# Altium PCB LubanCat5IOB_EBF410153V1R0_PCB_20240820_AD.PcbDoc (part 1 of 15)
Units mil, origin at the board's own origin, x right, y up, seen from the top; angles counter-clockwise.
Board outline 6811.02 x 4055.12 mil, 6 copper layers (TOP, GND02, ART03, ART04, PWR05, BOTTOM), stack 59.279 mil thick; 981 components, 783 nets, 3627 pads, 2669 vias.
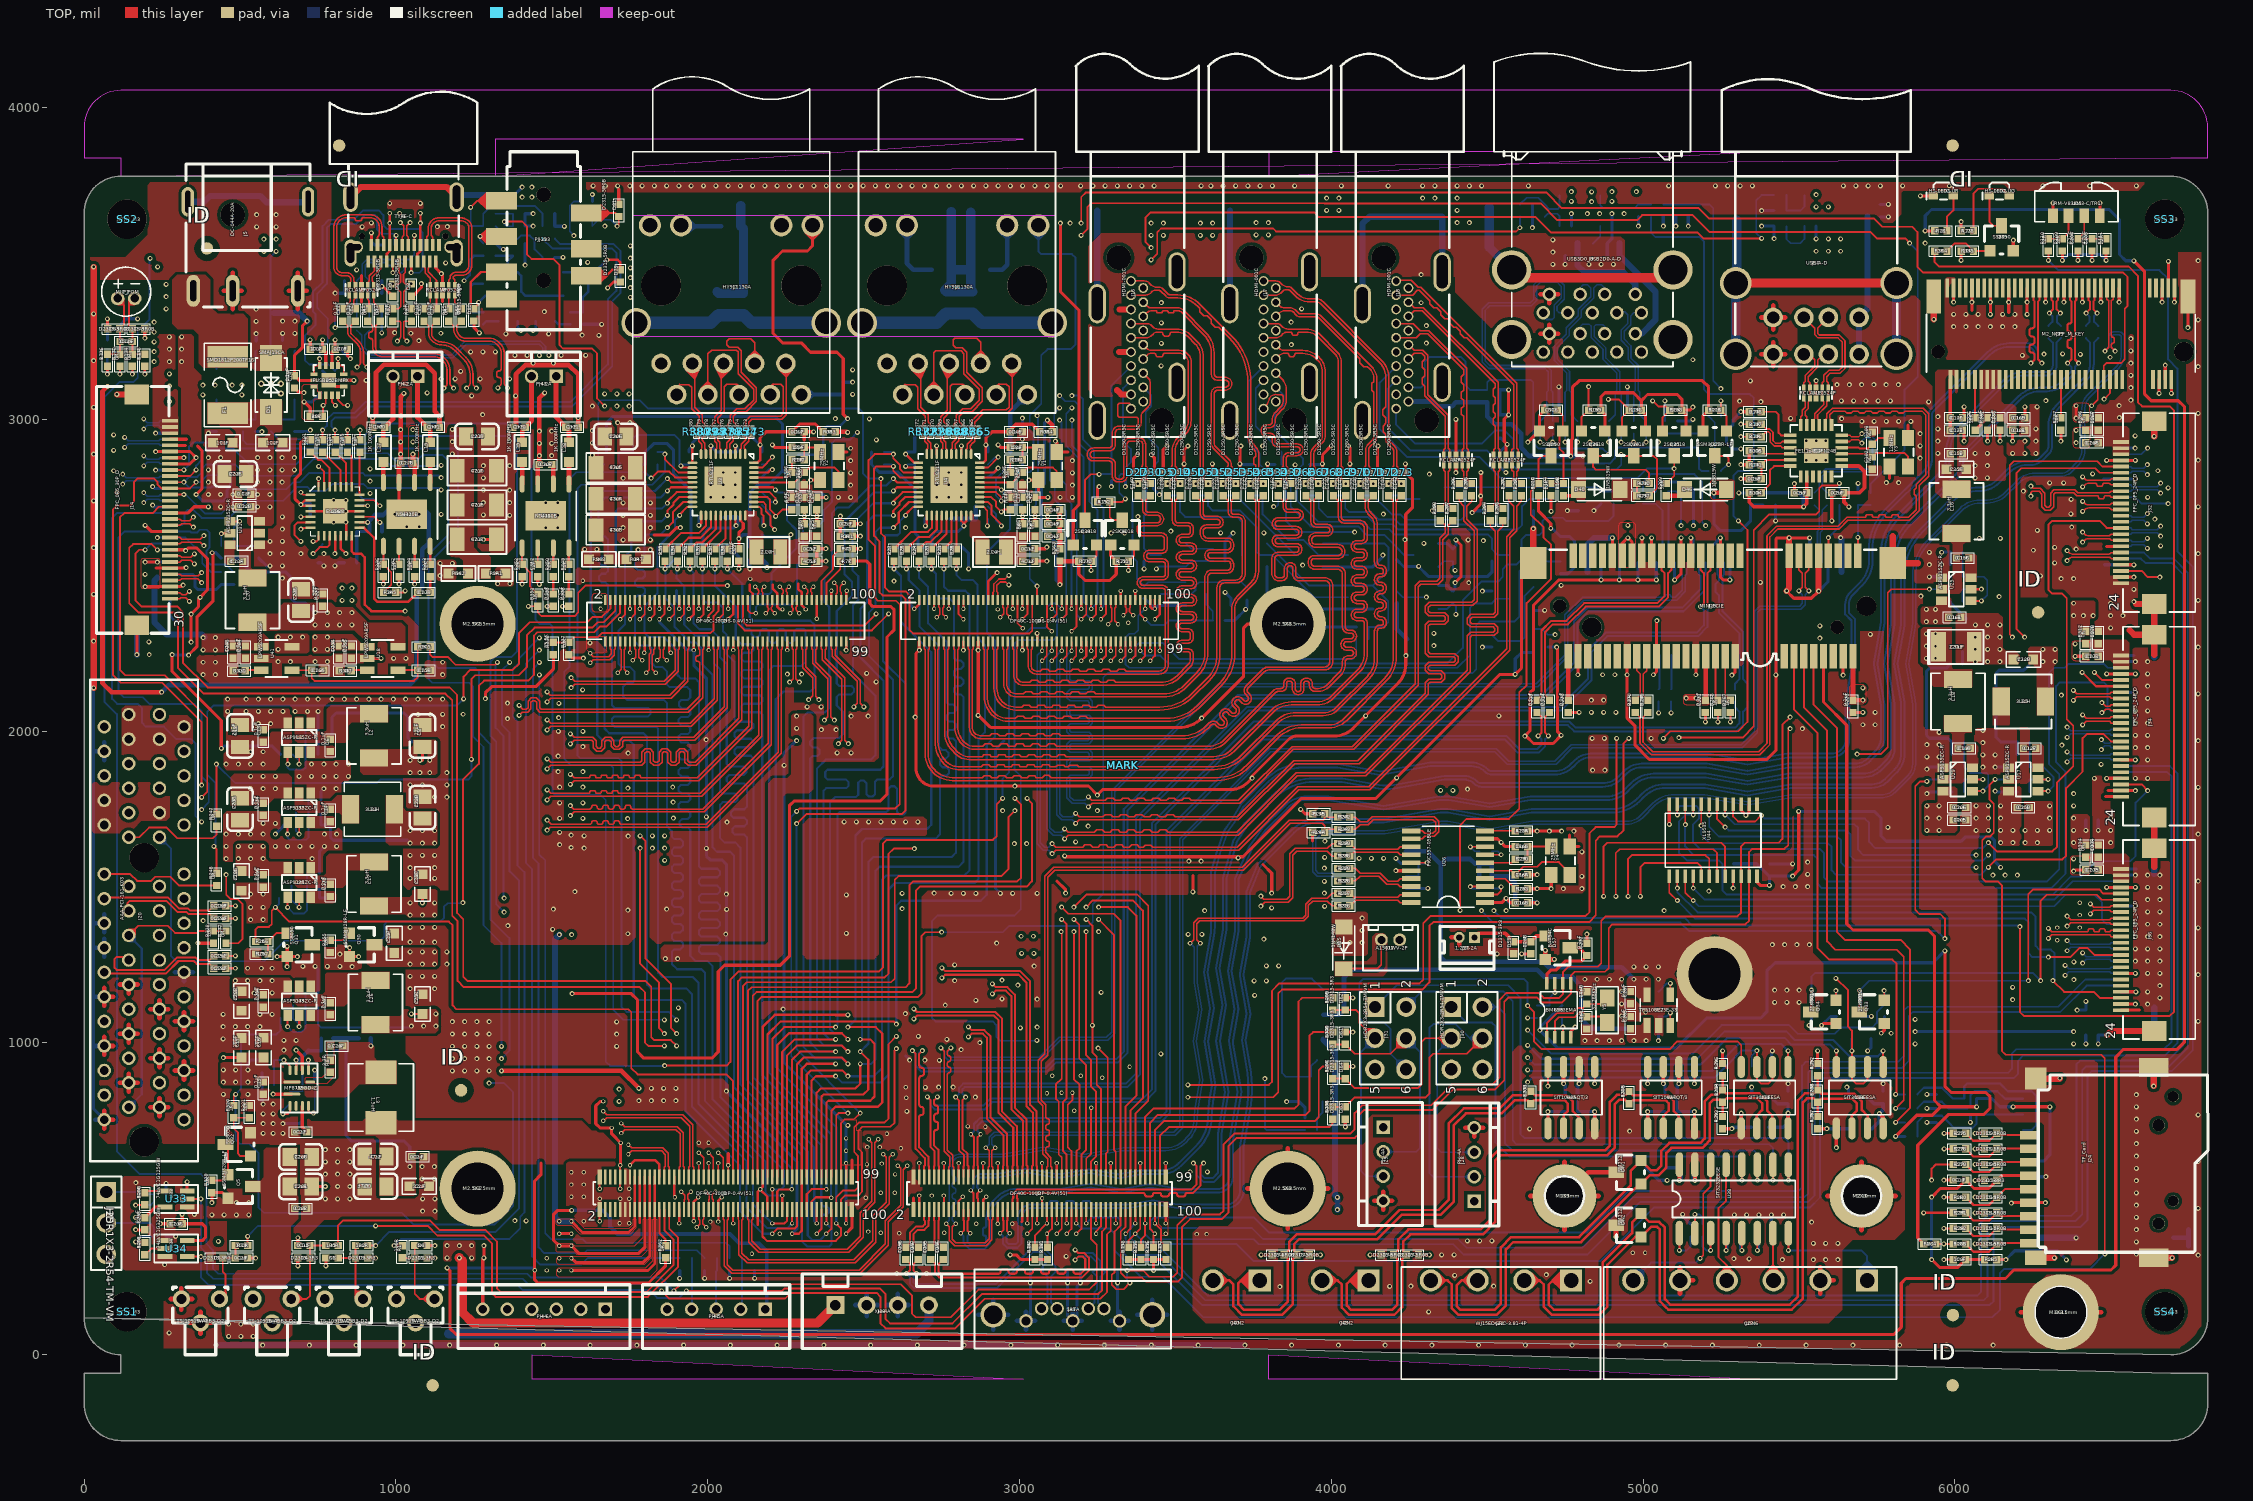
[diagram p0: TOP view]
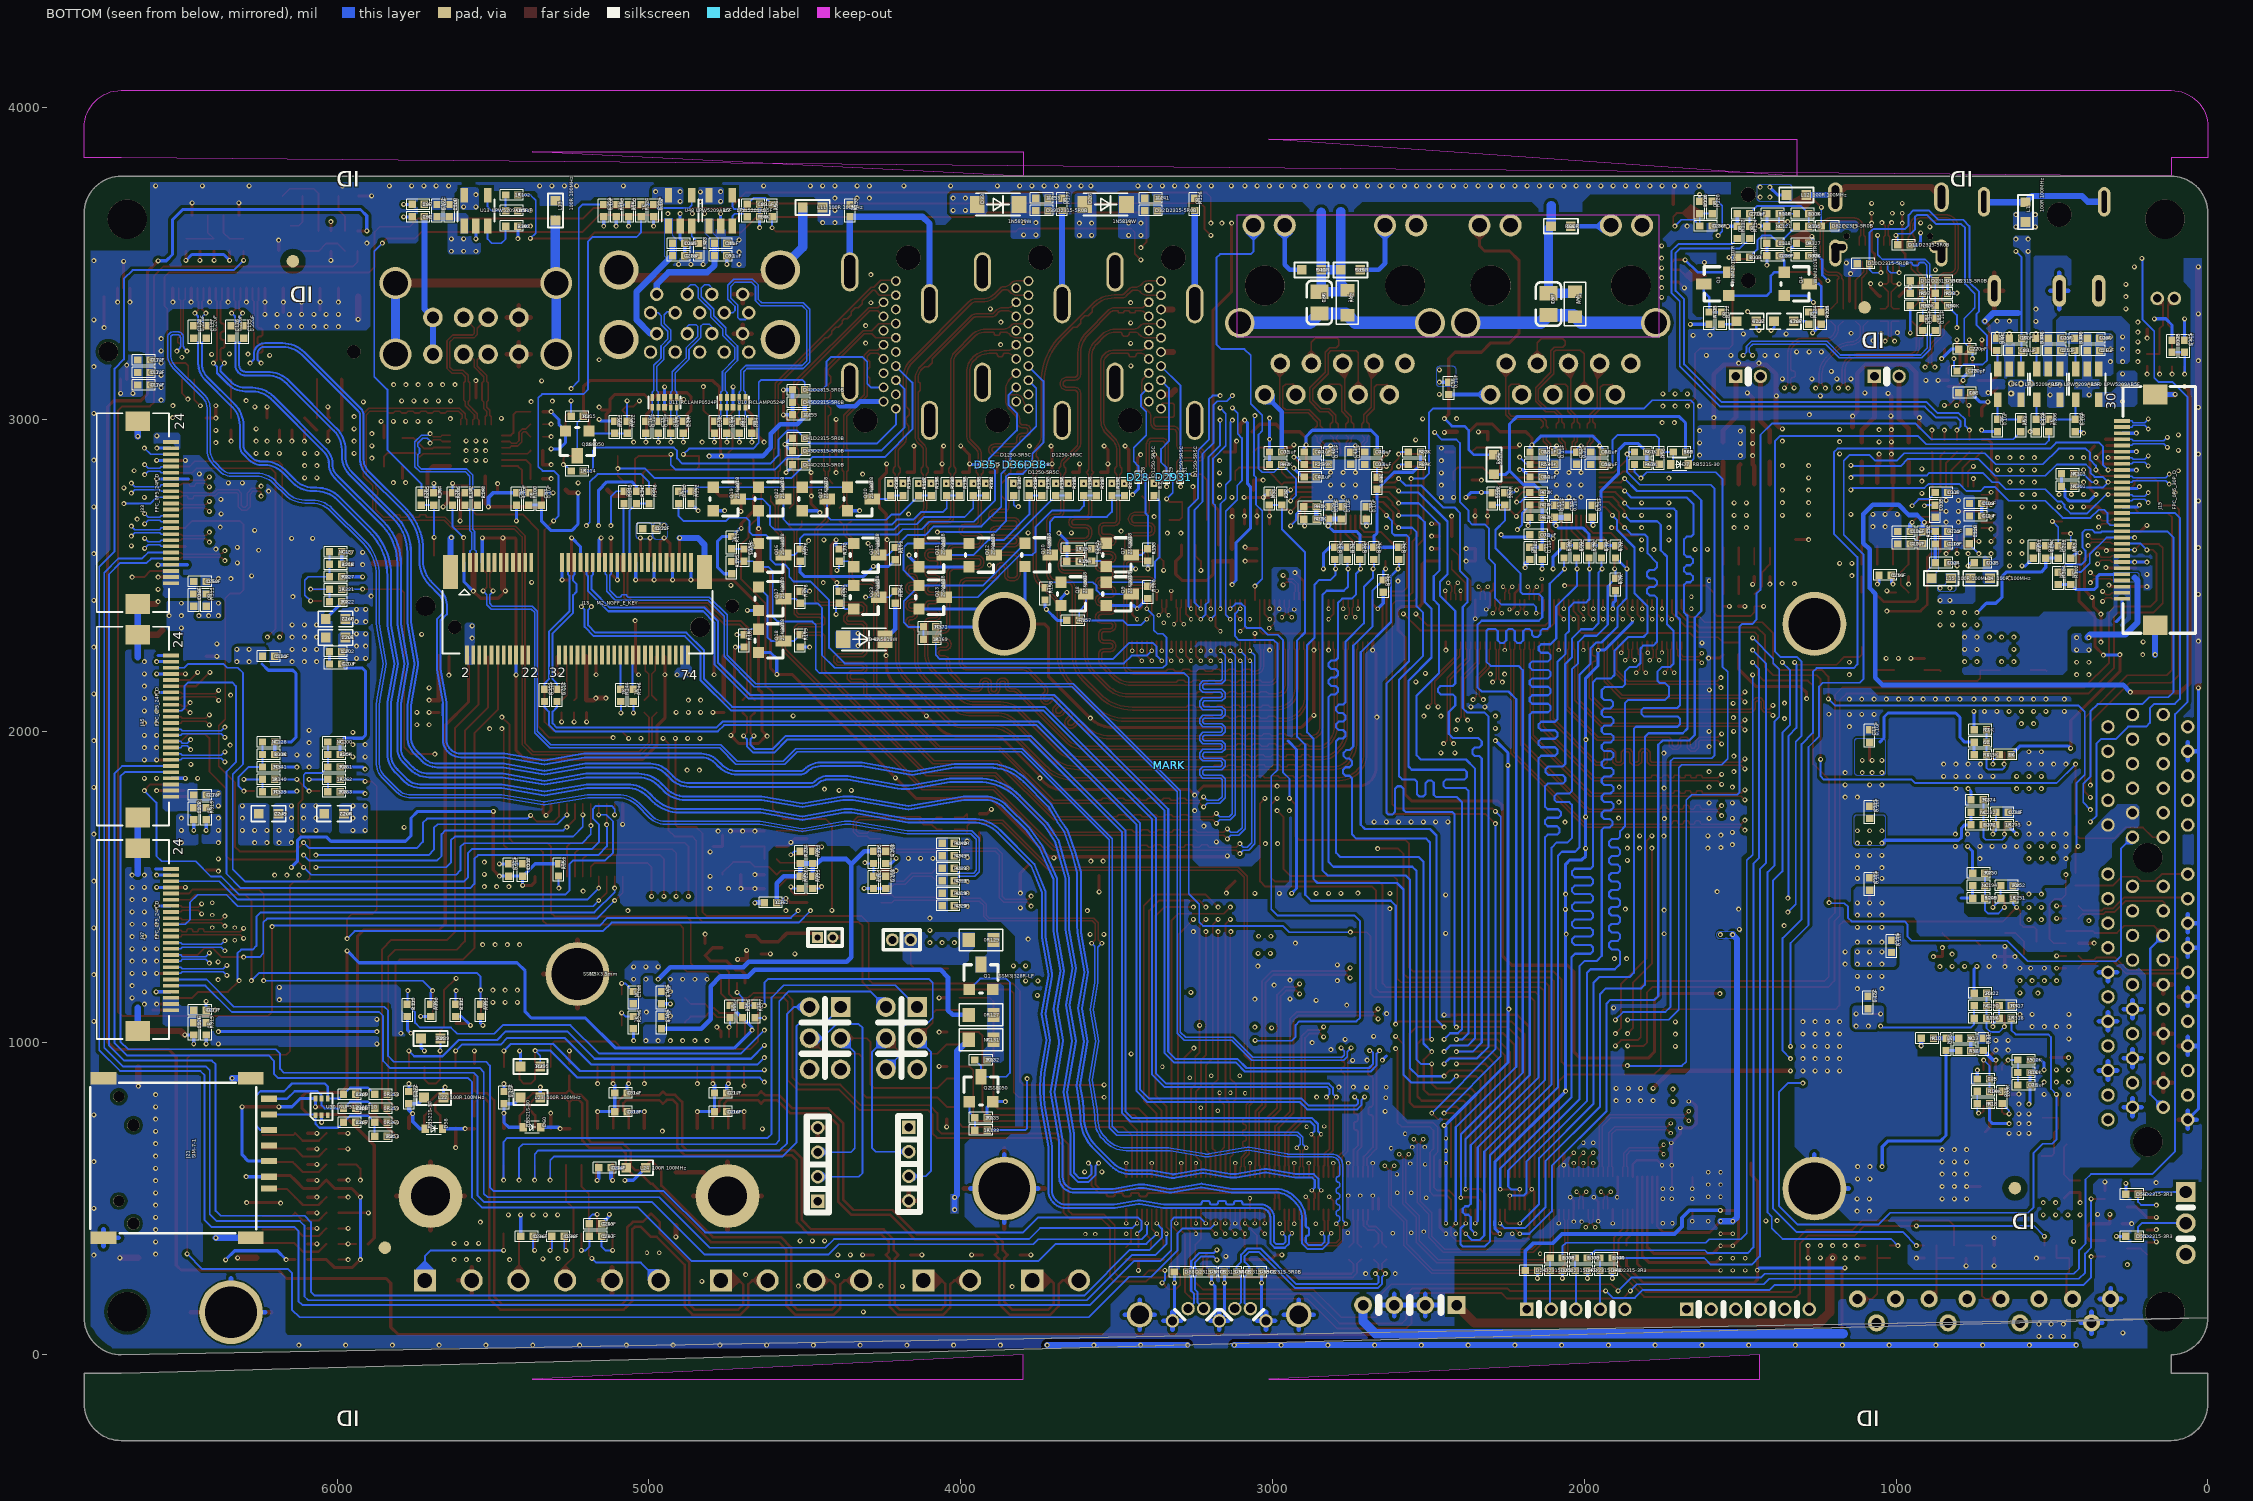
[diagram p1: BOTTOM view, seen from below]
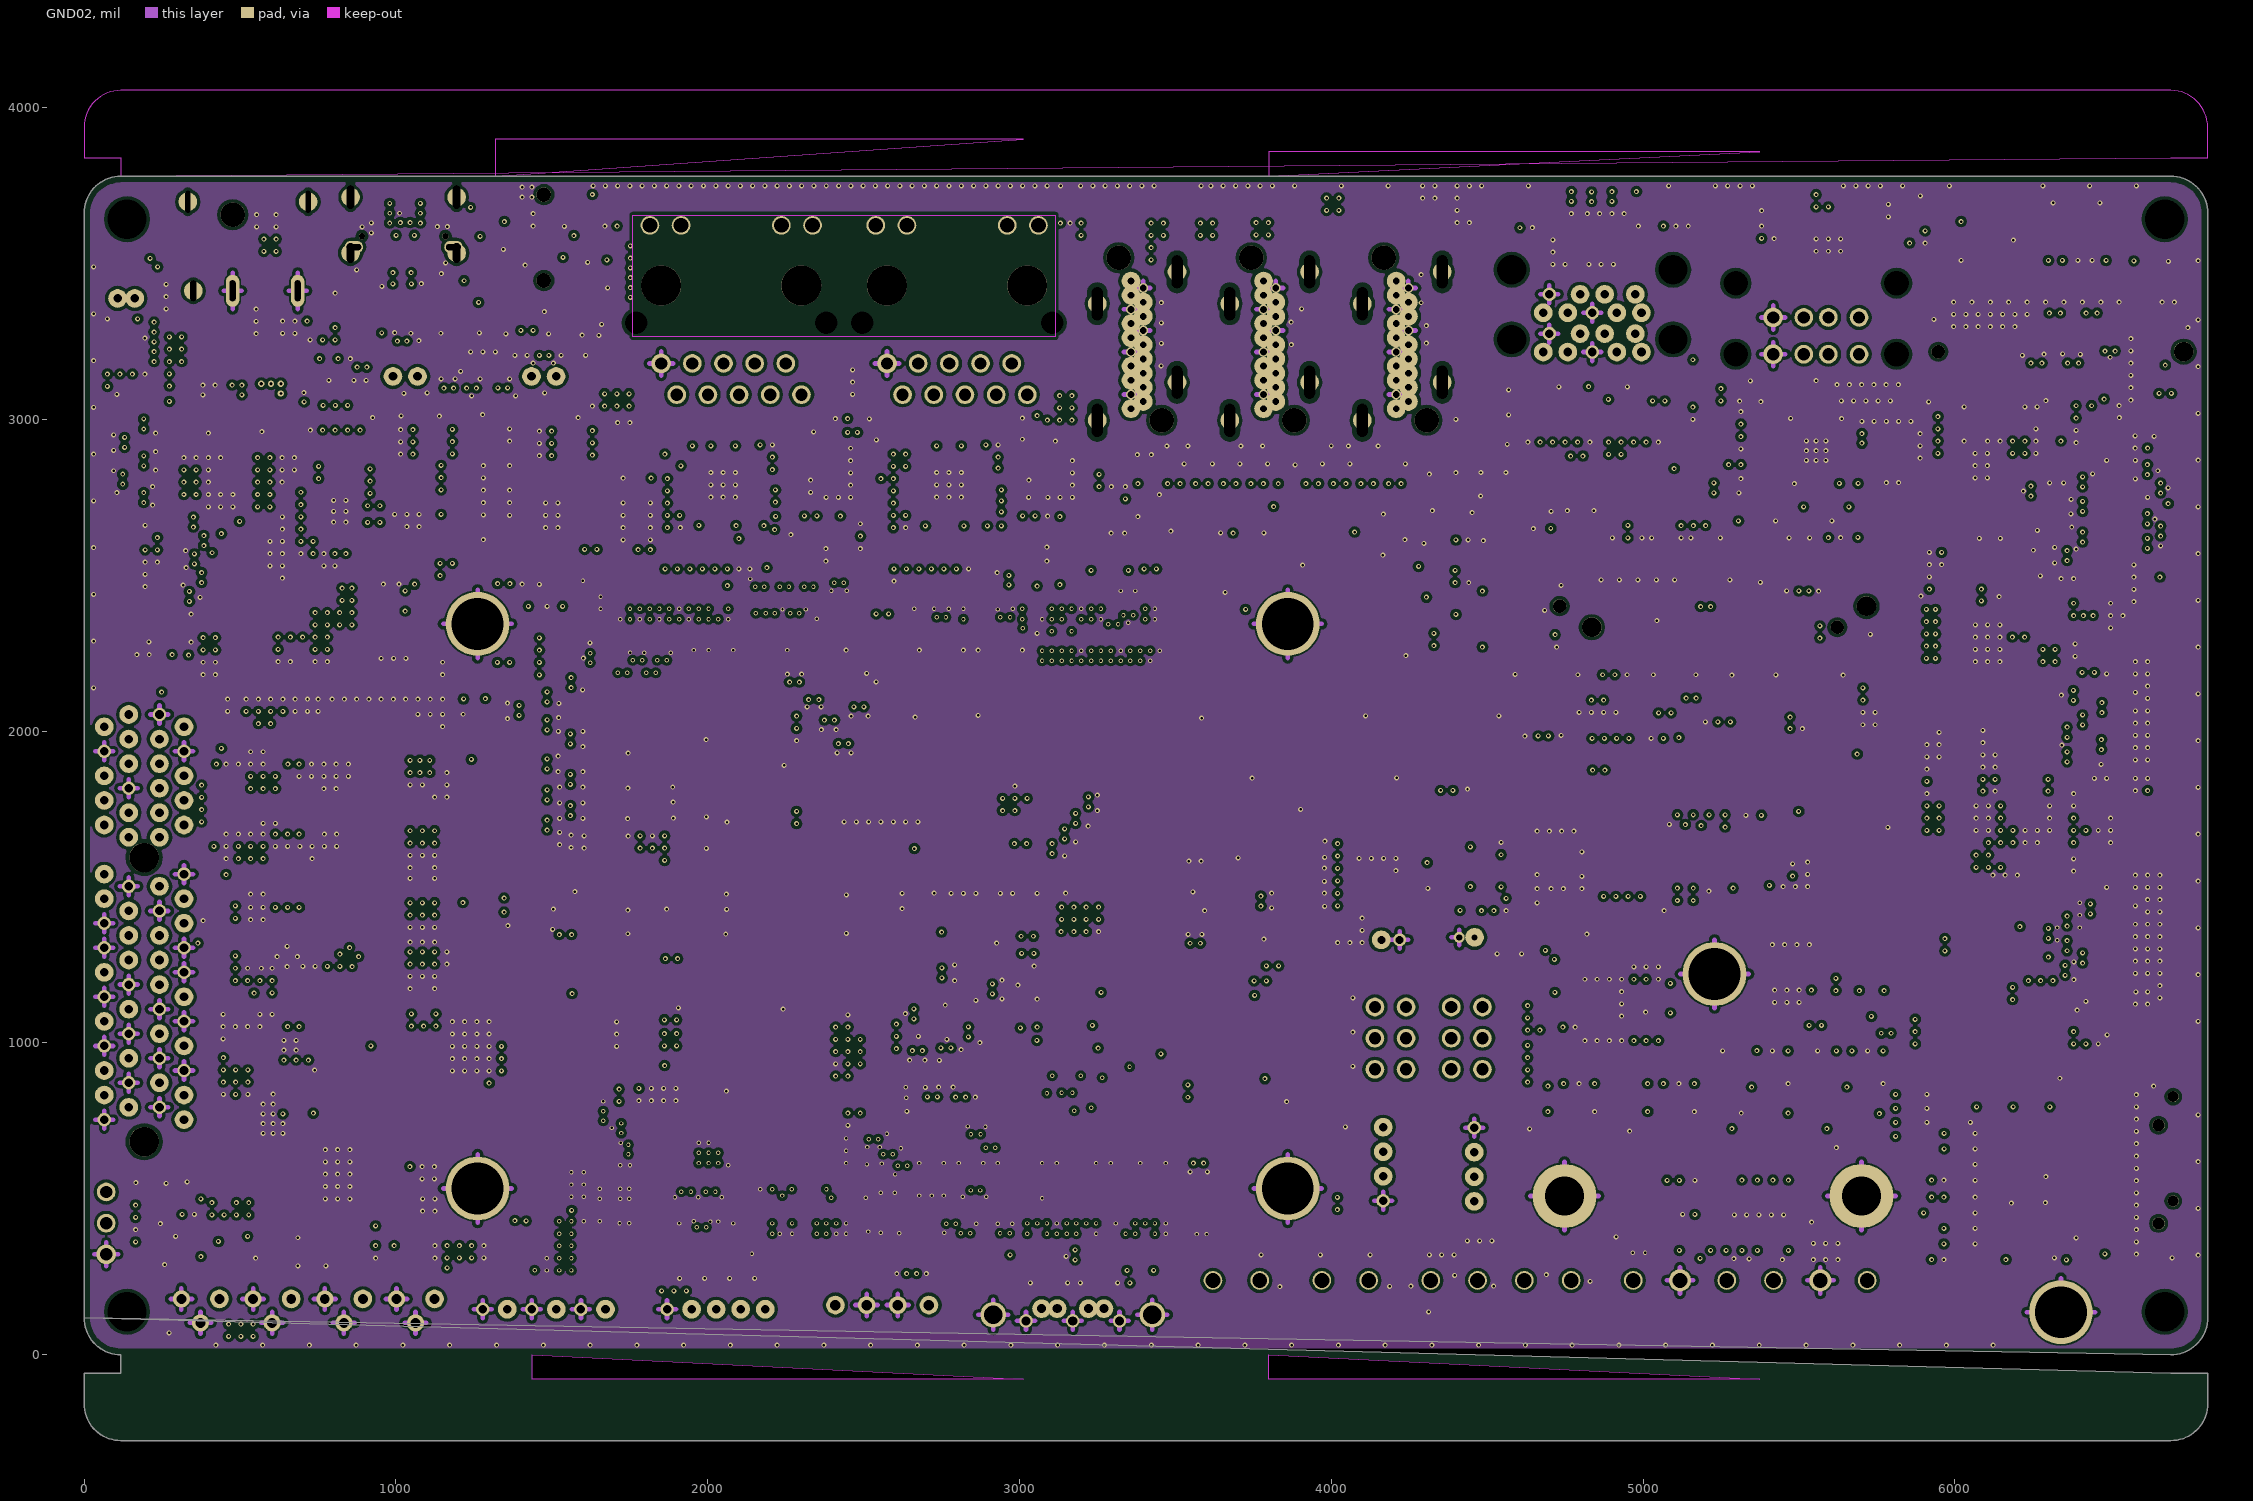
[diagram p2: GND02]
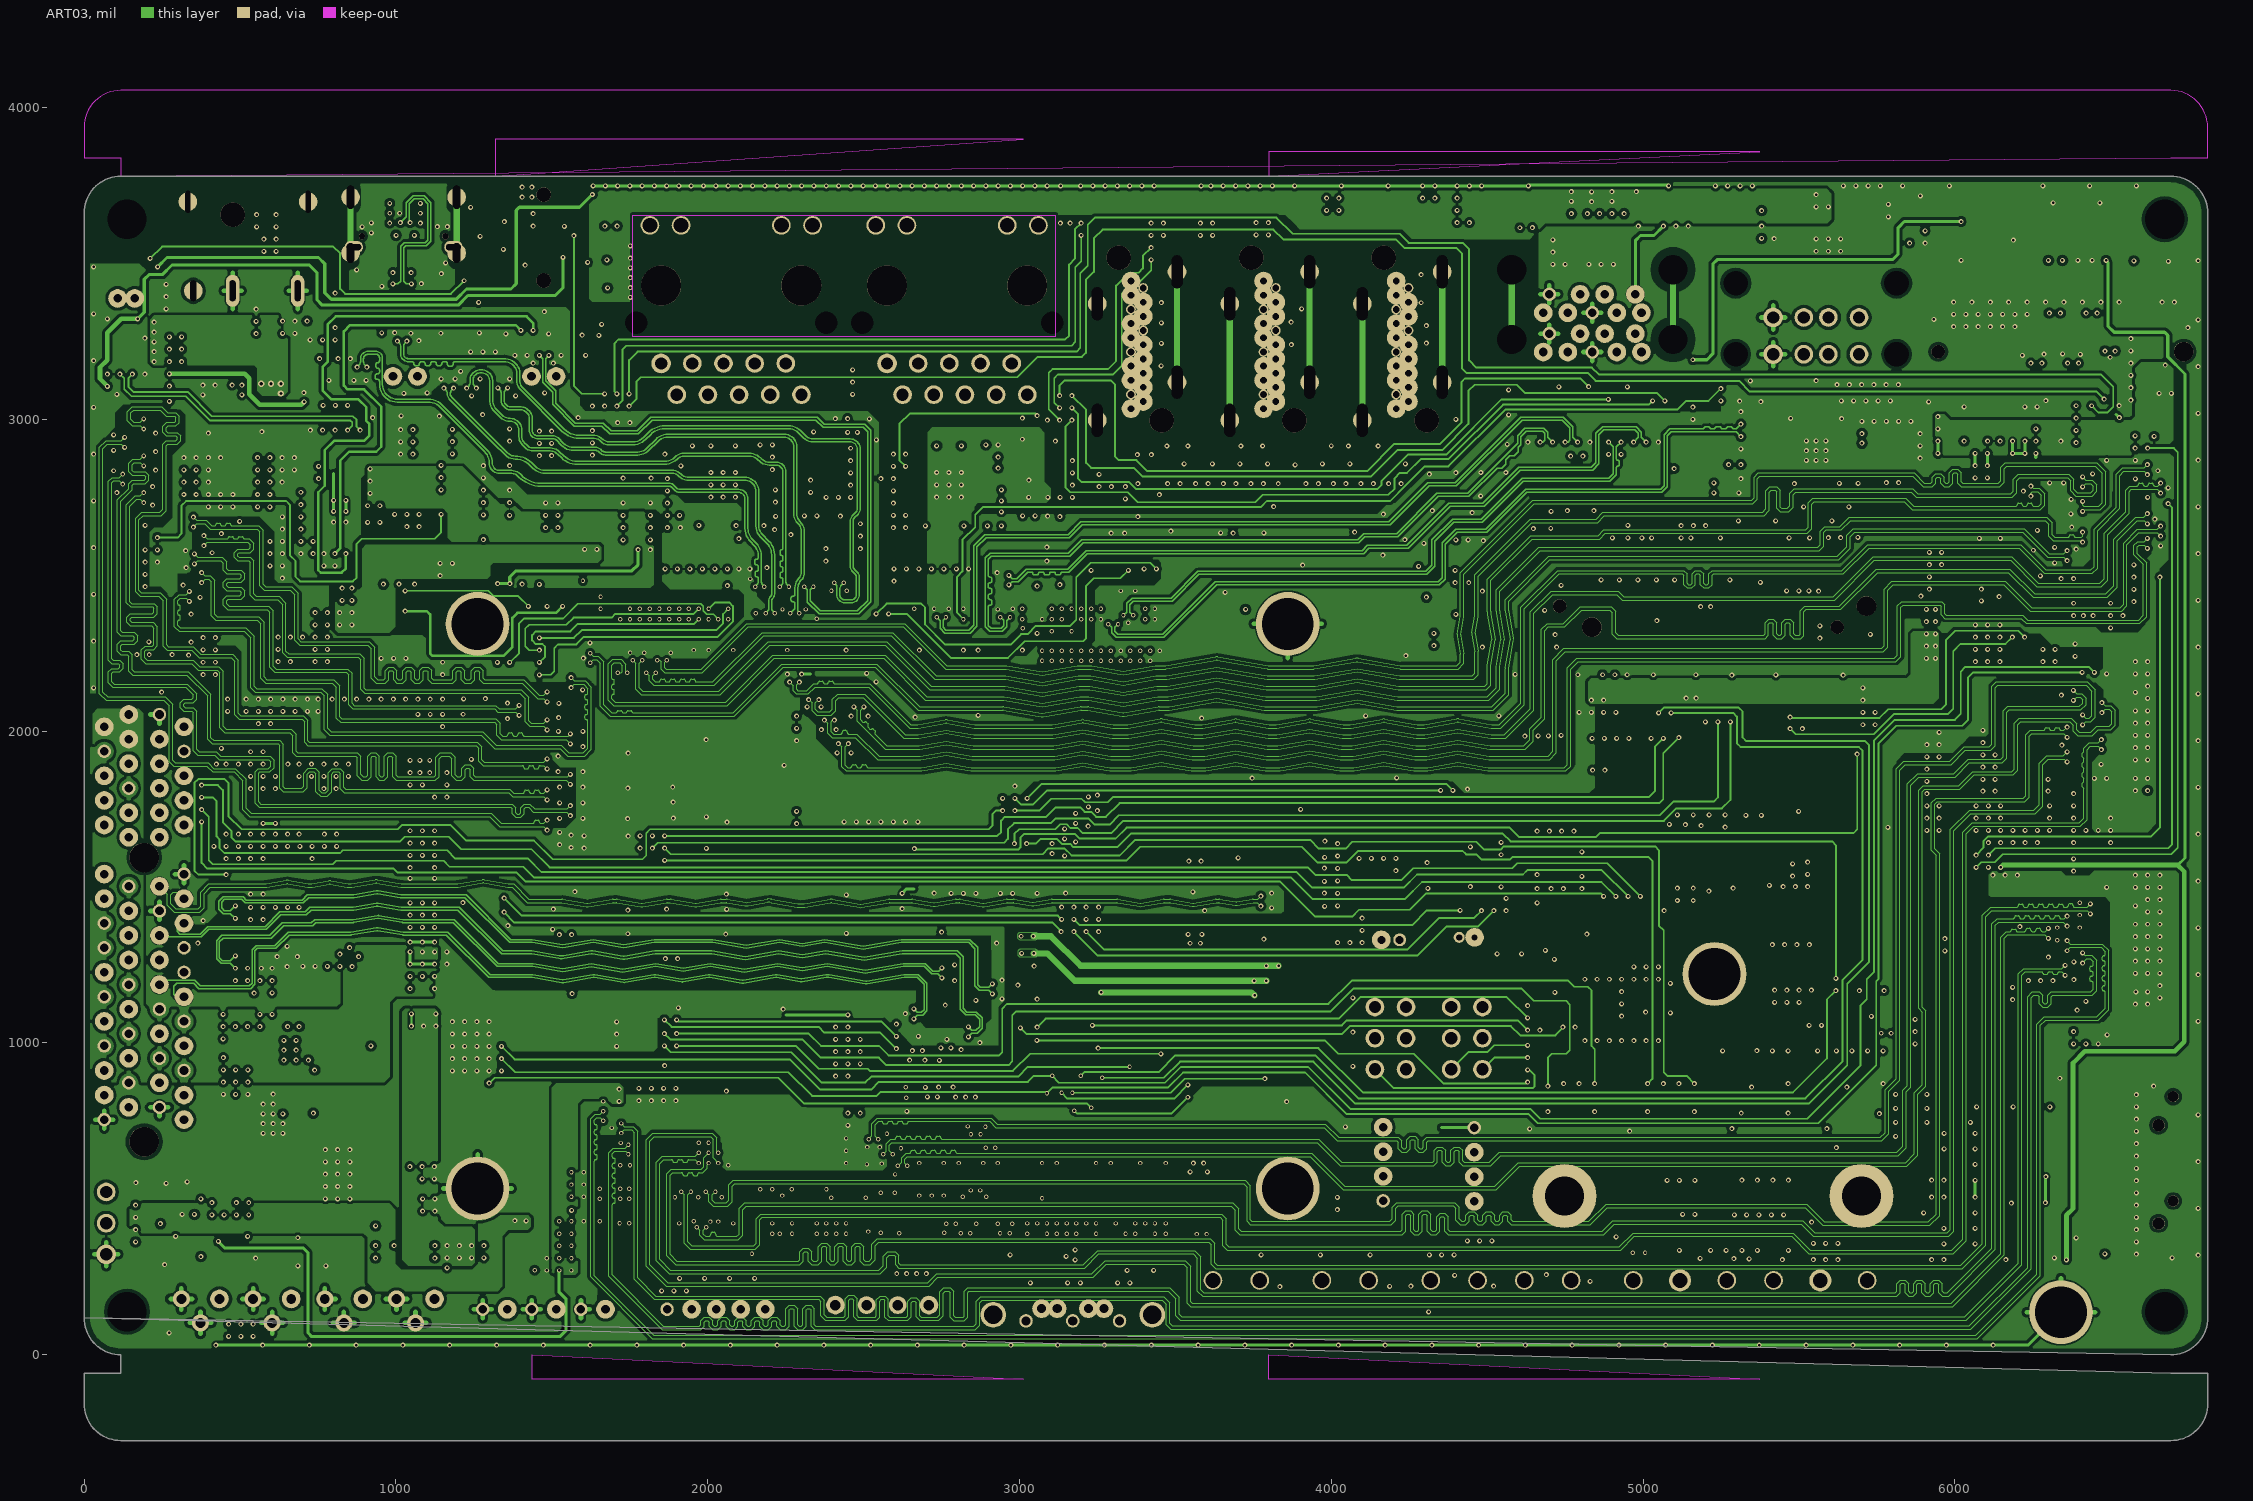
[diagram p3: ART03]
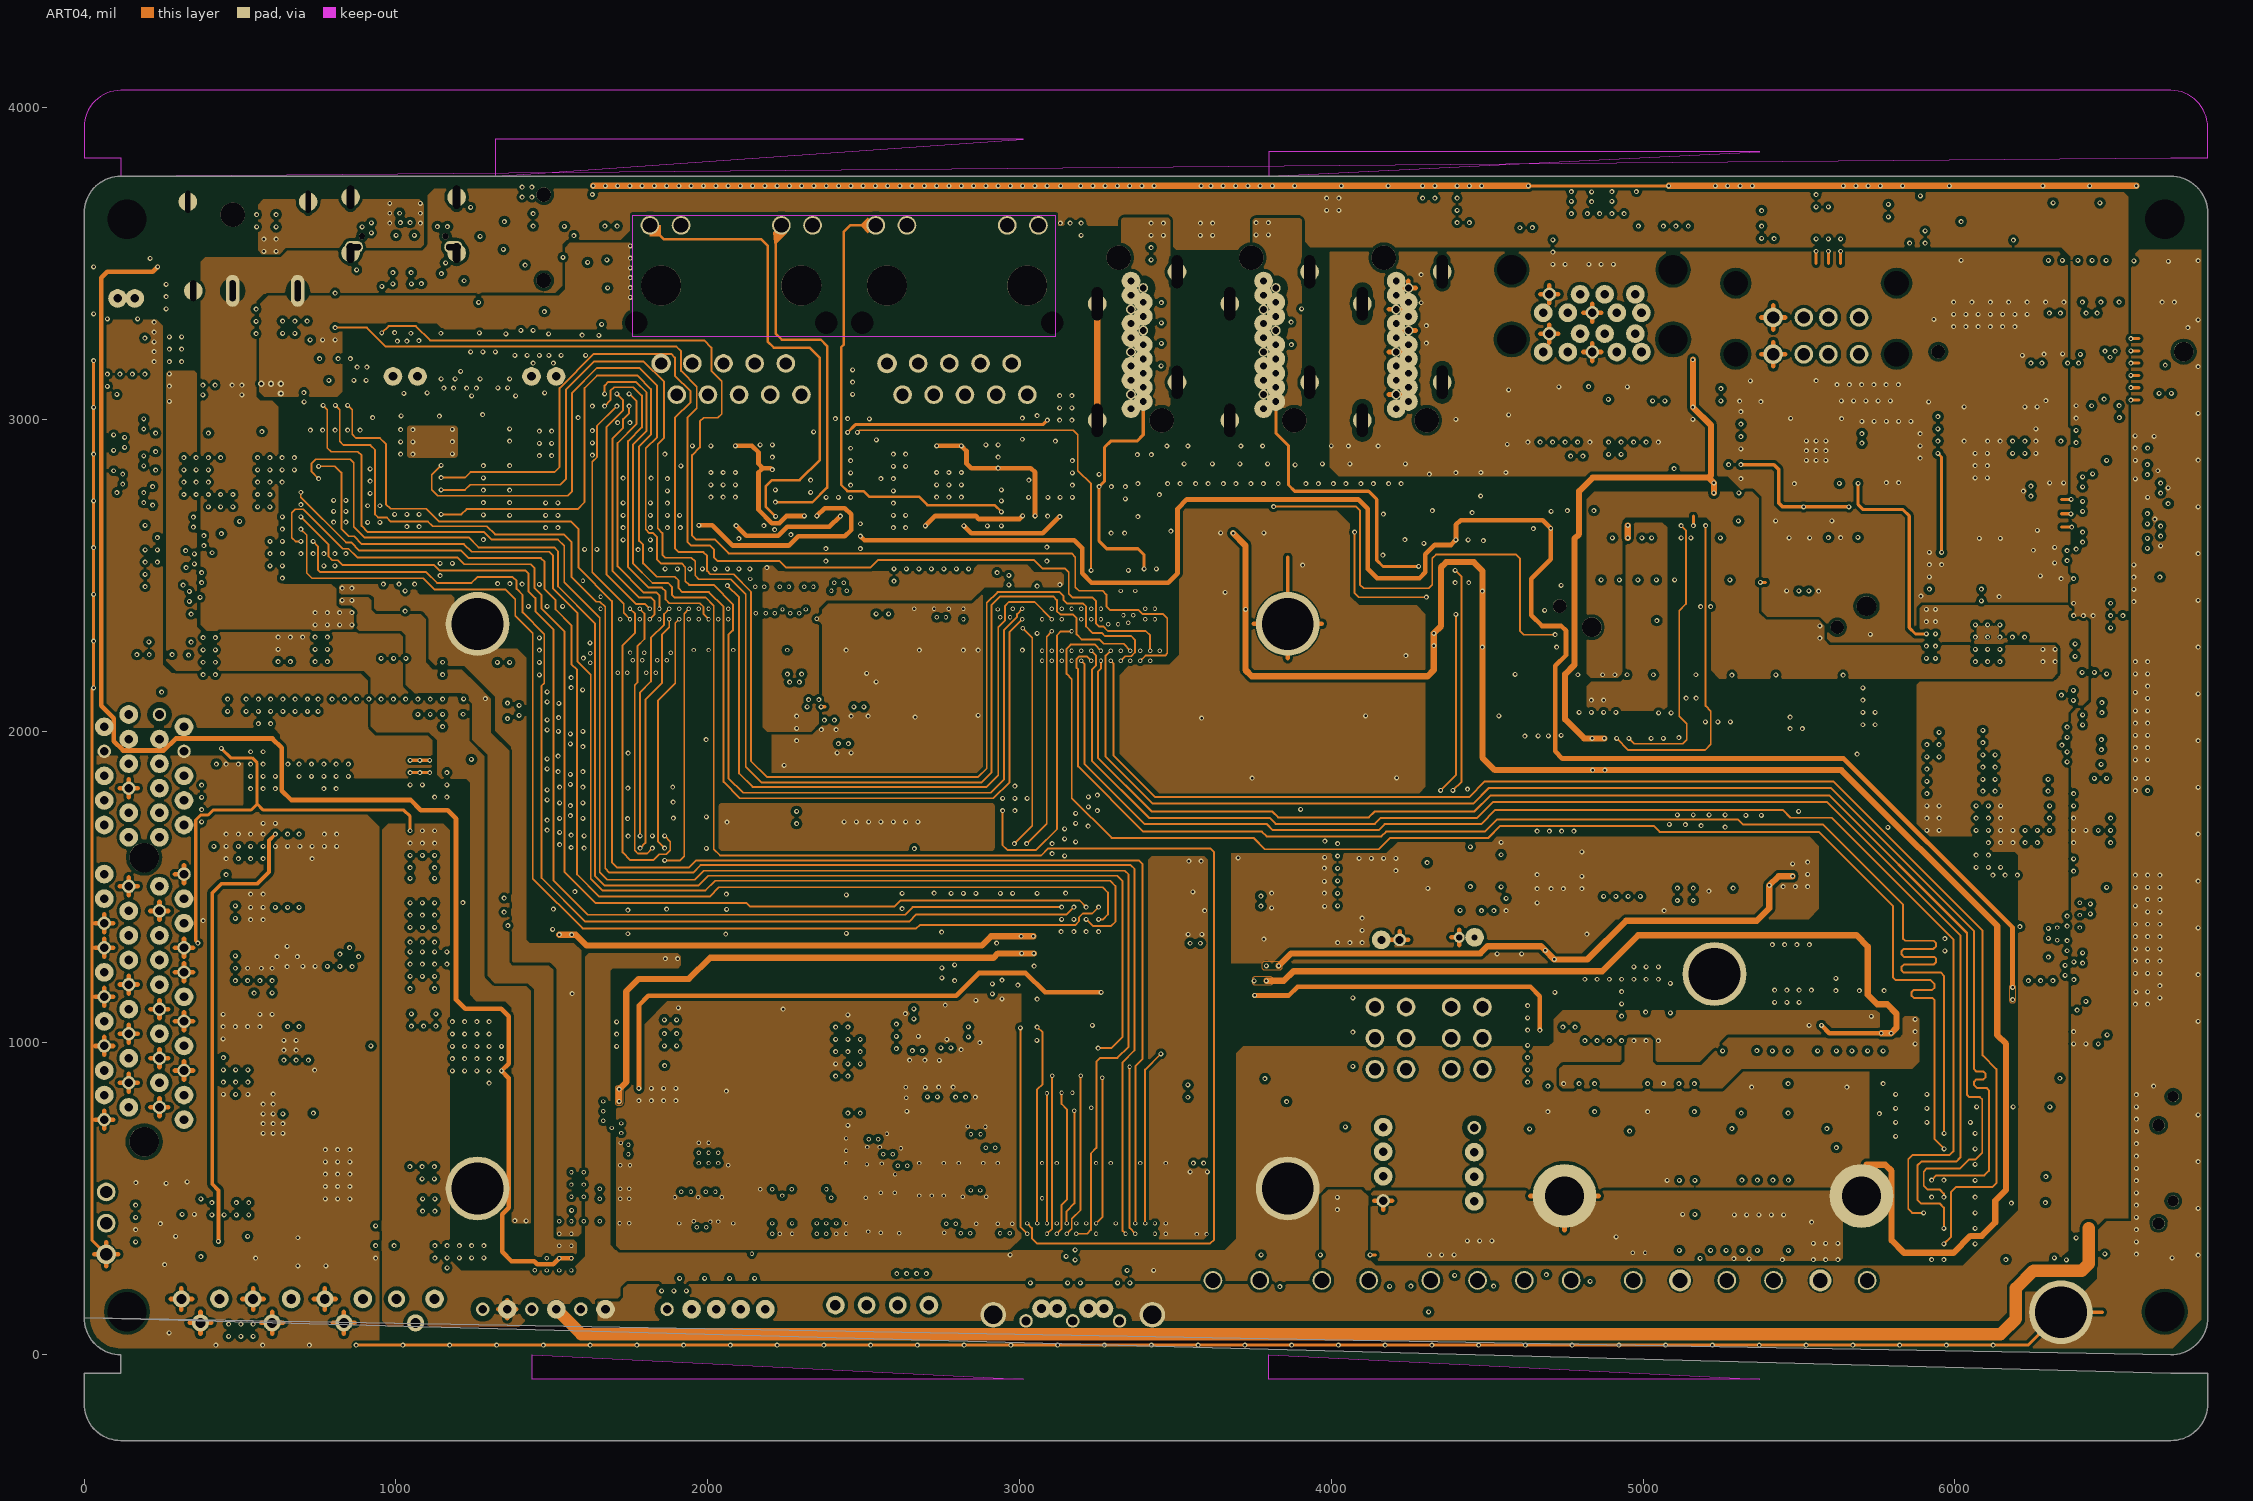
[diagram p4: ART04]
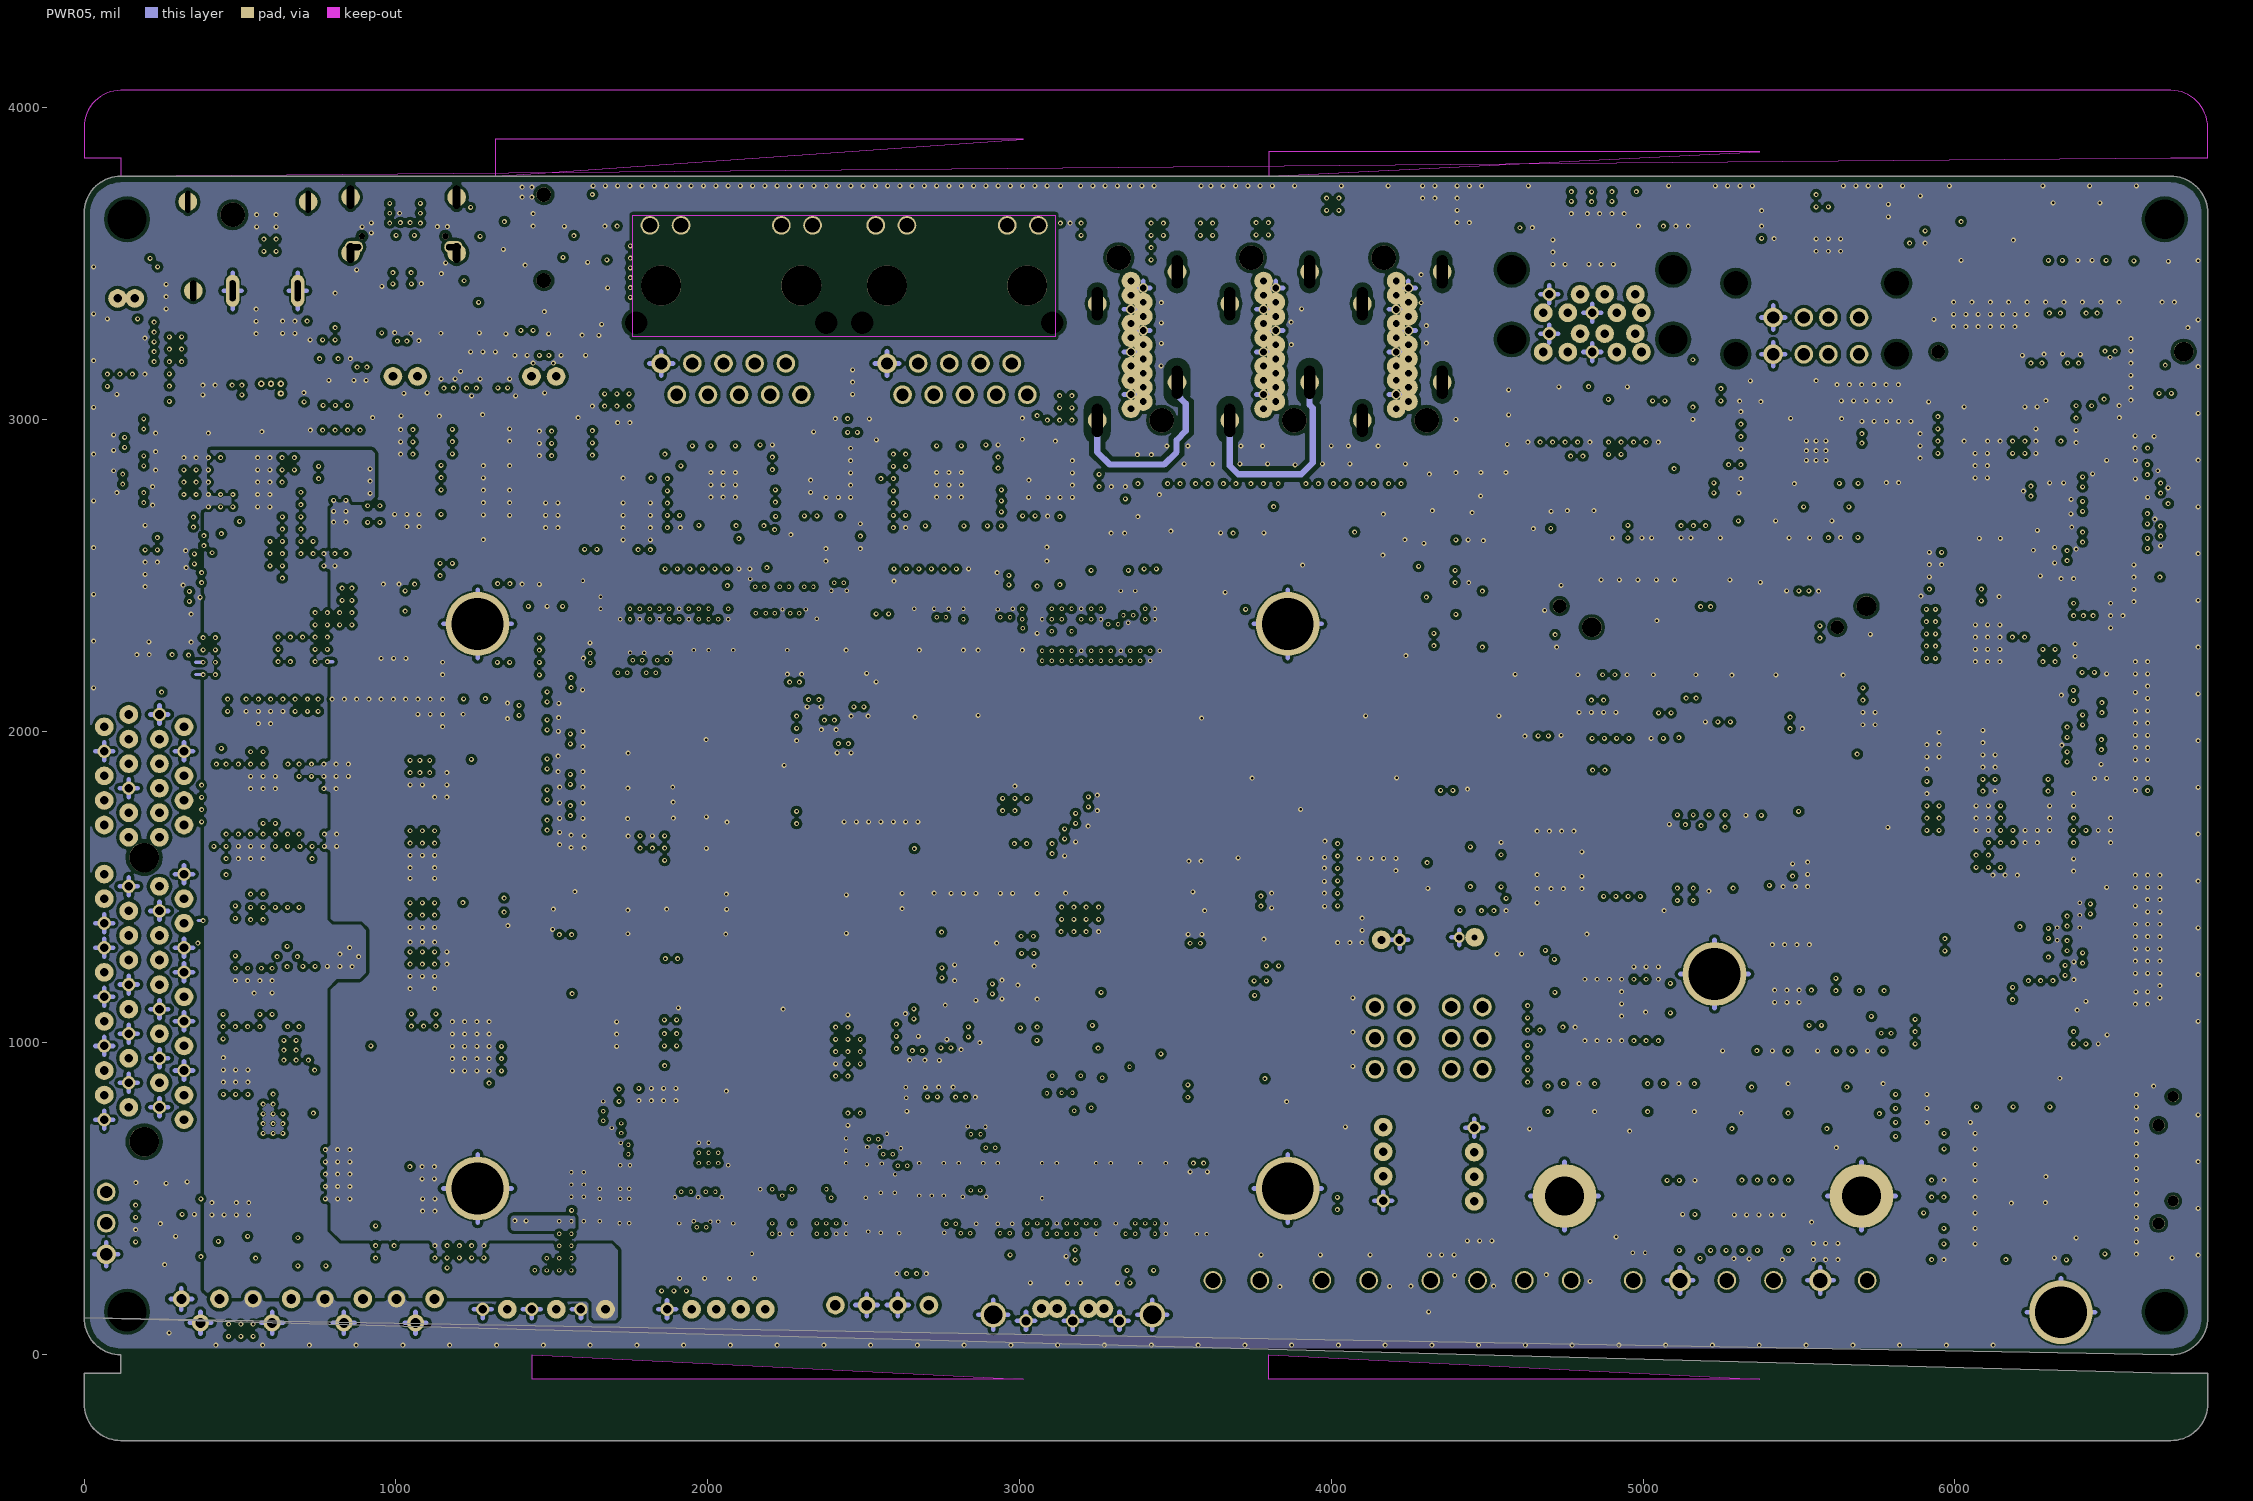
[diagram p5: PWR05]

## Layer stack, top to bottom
Top Solder: solder mask 0.4, Solder Resist, Dk 3.5
TOP: signal copper 0.71
Dielectric 1: core 4.3031, FR-4, Dk 4.5
GND02: signal copper 1.2
Dielectric2: core 5.1, FR-4, Dk 4.5
ART03: signal copper 1.2
Dielectric3: core 34.2529, FR-4, Dk 4.5
ART04: signal copper 1.2
Dielectric4: core 5.1, FR-4, Dk 4.5
PWR05: signal copper 1.2
Dielectric5: core 4.3031, FR-4, Dk 4.5
BOTTOM: signal copper 0.71
Bottom Solder: solder mask 0.4, Solder Resist, Dk 3.5

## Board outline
6692.91,-59.05 6811.02,-59.05 6811.02,-157.48 cw(c6692.91,-157.48) 118.11,-275.59 cw(c118.11,-157.48) 0,-59.05 118.11,-59.05 118.11,0 cw(c118.11,118.11) 6692.91,0 ccw(c6692.91,118.11) 6811.02,3661.42 ccw(c6692.91,3661.42) 118.11,3779.53 ccw(c118.11,3661.42) 0,118.11
cut-out: 6692.91,3838.58 6811.02,3838.58 6811.02,3937.01 ccw(c6692.91,3937.01) 118.11,4055.12 ccw(c118.11,3937.01) 0,3838.58 118.11,3838.58 118.11,3779.53
cut-out: 3011.81,-78.74 1437.01,-78.74 1437.01,0
cut-out: 5374.01,-78.74 3799.21,-78.74 3799.21,0
cut-out: 5374.01,3858.27 3799.21,3858.27 3799.21,3779.53
cut-out: 3011.81,3897.64 1318.9,3897.64 1318.9,3779.53

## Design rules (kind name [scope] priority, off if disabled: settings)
Clearance [All] p1: gap=10 ignorepadtopadclearanceinfootprint=FALSE except(0: Arc-Hole Track-Hole SMDPad-Hole THPad-Hole Via-Hole Fill-Hole Poly-Hole Region-Hole Text-Hole)
DiffPairsRouting [All] p1: maxlimit=10 minlimit=10 mostfreqgap=10 toplayer_minwidth=15 toplayer_maxwidth=15 toplayer_prefwidth=15 midlayer1_minwidth=15 midlayer1_maxwidth=15 midlayer1_prefwidth=15 midlayer2_minwidth=15 midlayer2_maxwidth=15 midlayer2_prefwidth=15 midlayer3_minwidth=15 midlayer3_maxwidth=15 midlayer3_prefwidth=15 midlayer4_minwidth=15 midlayer4_maxwidth=15 midlayer4_prefwidth=15 bottomlayer_minwidth=15 bottomlayer_maxwidth=15 bottomlayer_prefwidth=15 maxuncoupledlength=500
PlaneConnect [All] p1: planeconnectstyle=Direct reliefexpansion=20 reliefentries=4 reliefconductorwidth=10 reliefairgap=10
PolygonConnect [All] p1: connectstyle=Direct reliefconductorwidth=10 reliefentries=4 polygonreliefangle="90 Angle" airgapwidth=10
RoomDefinition RoomsKeepin1 [All vs False] p1: confinementstyle=ConfineIn formatcopy=TRUE lockcomponents=FALSE outline 6692.91,3739.53 6699.72,3739.23 6706.48,3738.34 6713.13,3736.87 6719.63,3734.82 6725.92,3732.21 6731.97,3729.06 6737.72,3725.4 6743.12,3721.25 6748.15,3716.65 6752.75,3711.63 6756.9,3706.22 6760.56,3700.47 6763.71,3694.43 6766.31,3688.13 6768.36,3681.63 6769.84,3674.98 6770.73,3668.22 6771.02,3661.42 6771.02,118.11 6770.73,111.3 6769.84,104.55 6768.36,97.89 6766.31,91.39 6763.71,85.1 6760.56,79.06 6756.9,73.31 6752.75,67.9 6748.15,62.88 6743.12,58.27 6737.72,54.13 6731.97,50.46 6725.92,47.32 6719.63,44.71 6713.13,42.66 6706.48,41.19 6699.72,40.3 6692.91,40 118.11,40 111.3,40.3 104.55,41.19 97.89,42.66 91.39,44.71 85.1,47.32 79.06,50.46 73.31,54.13 67.9,58.27 62.88,62.88 58.27,67.9 54.13,73.31 50.46,79.06 47.32,85.1 44.71,91.39 42.66,97.89 41.19,104.55 40.3,111.3 40,118.11 40,3661.42 40.3,3668.22 41.19,3674.98 42.66,3681.63 44.71,3688.13 47.32,3694.43 50.46,3700.47 54.13,3706.22 58.27,3711.63 62.88,3716.65 67.9,3721.25 73.31,3725.4 79.06,3729.06 85.1,3732.21 91.39,3734.82 97.89,3736.87 104.55,3738.34 111.3,3739.23 118.11,3739.53 6692.91,3739.53
RoomDefinition RoomsKeepin0 [All vs False] p2: confinementstyle=ConfineIn formatcopy=TRUE lockcomponents=FALSE outline 6692.91,3739.53 6699.72,3739.23 6706.48,3738.34 6713.13,3736.87 6719.63,3734.82 6725.92,3732.21 6731.97,3729.06 6737.72,3725.4 6743.12,3721.25 6748.15,3716.65 6752.75,3711.63 6756.9,3706.22 6760.56,3700.47 6763.71,3694.43 6766.31,3688.13 6768.36,3681.63 6769.84,3674.98 6770.73,3668.22 6771.02,3661.42 6771.02,118.11 6770.73,111.3 6769.84,104.55 6768.36,97.89 6766.31,91.39 6763.71,85.1 6760.56,79.06 6756.9,73.31 6752.75,67.9 6748.15,62.88 6743.12,58.27 6737.72,54.13 6731.97,50.46 6725.92,47.32 6719.63,44.71 6713.13,42.66 6706.48,41.19 6699.72,40.3 6692.91,40 118.11,40 111.3,40.3 104.55,41.19 97.89,42.66 91.39,44.71 85.1,47.32 79.06,50.46 73.31,54.13 67.9,58.27 62.88,62.88 58.27,67.9 54.13,73.31 50.46,79.06 47.32,85.1 44.71,91.39 42.66,97.89 41.19,104.55 40.3,111.3 40,118.11 40,3661.42 40.3,3668.22 41.19,3674.98 42.66,3681.63 44.71,3688.13 47.32,3694.43 50.46,3700.47 54.13,3706.22 58.27,3711.63 62.88,3716.65 67.9,3721.25 73.31,3725.4 79.06,3729.06 85.1,3732.21 91.39,3734.82 97.89,3736.87 104.55,3738.34 111.3,3739.23 118.11,3739.53 6692.91,3739.53
RoutingVias [All] p1: holewidth=28 width=50 viastyle="Through Hole" minholewidth=28 minwidth=50 maxholewidth=28 maxwidth=50
SolderMaskExpansion [All] p1: expansion=4 istentingtop=FALSE
Width [All] p1: maxlimit=10 minlimit=10 preferedwidth=10 impedanceprofiledriven=TRUE minimp=3.070000 maximp=3.070000 favimp=3.070000
28 further rules are at their usual default settings.

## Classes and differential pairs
net class CLS_CLK: RTC_32K_IN
net class HDMI_GND: N16778784 N16781438 N16783799
net class GND: GND
net class 50_OHM: GMAC0_MCLKINOUT GMAC0_RXCLK GMAC0_RXD0 GMAC0_RXD1 GMAC0_RXD2 GMAC0_RXD3 GMAC0_RXDV_CRS GMAC0_TXCLK GMAC0_TXD0 GMAC0_TXD1 GMAC0_TXD2 GMAC0_TXD3 GMAC0_TXEN GMAC1_RXCLK GMAC1_RXD0 GMAC1_RXD1 GMAC1_RXD2 GMAC1_RXD3 GMAC1_RXDV_CRS GMAC1_TXCLK GMAC1_TXD0 GMAC1_TXD1 GMAC1_TXD2 GMAC1_TXD3 GMAC1_TXEN SDMMC_CLK SDMMC_CMD SDMMC_D0 SDMMC_D1 SDMMC_D2 SDMMC_D3
net class PWR: 1V05_AVDD_PHY0 1V05_AVDD_PHY1 1V05_DVDD_PHY0 1V05_DVDD_PHY1 1V05_PHY0 1V05_PHY1 1V8_DVDD_PHY1 3V3_AVDD_PHY0 3V3_AVDD_PHY1 3V3_DVDD_PHY0 3V3_DVDD_PHY1 12V_DC HDMI0_5V HDMI1_5V M2EKEY_3V3 M2PCIE_3V3 MINIPCIE_3V3 RS232_3V3 RS485_2_3V3 SIM_VDD VCC3V3_PCIECLK VCC3V3_PCIEX4 VCC3V3_SD_S3 VCC4V0_SYS VCC5V0_HDMI_RX VCC5V0_USB20_HOST VCC5V0_USB20_HUB VCC5V0_USB30_OTG VCC5V0_USB_S0 VCC12V_PCIEX4 VCC_1V8_S0 VCC_1V8_S3 VCC_3V3_S0 VCC_3V3_S3 VCC_5V0_S0 VCC_12V VCC_RTC VCCA1V8_CODEC VCCA3V3_CODEC VCCA_1V8_S0 VCCA_3V3_S0 VDD_CAM0_5V VDD_CAM1_5V VDD_CAM2_5V VDD_CAM3_5V VDD_CAM4_5V VDD_CAM5_5V VDD_LCD0_3V3 VDD_LCD0_5V VDD_LCD1_3V3 VDD_LCD1_5V
differential pair USB30_TX: +USB30_TXN -USB30_TXP
differential pair USB30_RX: +USB30_RXN -USB30_RXP
differential pair DP6: +USB30_DM -USB30_DP
differential pair DP1: +USB20_HOST1_DM -USB20_HOST1_DP
differential pair DP7: +USB20_HOST0_DM -USB20_HOST0_DP
differential pair DP7: +USB20_DP1 -USB20_HOST0_DM
differential pair DP7: +USB20_DM1 -USB20_DP1
differential pair DP2: +USB_HUB_DM4 -USB_HUB_DP4
differential pair DP3: +USB_HUB_DM3 -USB_HUB_DP3
differential pair DP4: +USB_HUB_DM2 -USB_HUB_DP2
differential pair DP5: +USB_HUB_DM1 -USB_HUB_DP1
differential pair DP6: +TYPEC1_USB20_OTG_DP -USB30_DM
differential pair DP6: +TYPEC1_USB20_OTG_DM -TYPEC1_USB20_OTG_DP
differential pair TYPEC1_SSTX1: +TYPEC1_SSTX1N -TYPEC1_SSTX1P
differential pair TYPEC1_SSRX1: +TYPEC1_SSRX1N -TYPEC1_SSRX1P
differential pair DP8: +TYPEC0_USB20_OTG_DM -TYPEC0_USB20_OTG_DP
differential pair DP10: +TYPEC0_SSTX2N -TYPEC0_SSTX2P
differential pair DP11: +TYPEC0_SSTX1N -TYPEC0_SSTX1P
differential pair DP9: +TYPEC0_SSRX2N -TYPEC0_SSRX2P
differential pair DP12: +TYPEC0_SSRX1N -TYPEC0_SSRX1P
differential pair DP13: +TYPEC0_SBU1 -TYPEC0_SBU2
differential pair DP13: +TYPEC_SUB2 -TYPEC0_SBU1
differential pair DP13: +TYPEC_SUB1 -TYPEC_SUB2
differential pair DP10: +TYPEC_SSTXP2 -TYPEC0_SSTX2N
differential pair DP11: +TYPEC_SSTXP1 -TYPEC0_SSTX1N
differential pair DP10: +TYPEC_SSTXN2 -TYPEC_SSTXP2
differential pair DP11: +TYPEC_SSTXN1 -TYPEC_SSTXP1
differential pair DP9: +TYPEC_SSRXP2 -TYPEC0_SSRX2N
differential pair DP12: +TYPEC_SSRXP1 -TYPEC0_SSRX1N
differential pair DP9: +TYPEC_SSRXN2 -TYPEC_SSRXP2
differential pair DP12: +TYPEC_SSRXN1 -TYPEC_SSRXP1
differential pair DP8: +TYPEC_DP -TYPEC0_USB20_OTG_DM
differential pair DP8: +TYPEC_DM -TYPEC_DP
differential pair DIFF_SATA30_0_TX: +SATA30_0_TXN -SATA30_0_TXP
differential pair DIFF_SATA30_0_RX: +SATA30_0_RXN -SATA30_0_RXP
differential pair DIFF_SATA30_0_TX: +SATA_TXP -SATA30_0_TXN
differential pair DIFF_SATA30_0_TX: +SATA_TXN -SATA_TXP
differential pair DIFF_SATA30_0_RX: +SATA_RXP -SATA30_0_RXN
differential pair DIFF_SATA30_0_RX: +SATA_RXN -SATA_RXP
differential pair PCIE30_PORT0_TX1: +PETN1 -PETP1
differential pair PCIE30_PORT0_TX0: +PETN0 -PETP0
differential pair PCIE20_2_TX: +PE_TXN -PE_TXP
differential pair PCIEX4_REF_CLK: +PCIEX4_REF_CLKN -PCIEX4_REF_CLKP
differential pair PCIE30_PORT1_TX1: +PCIEX4_PETN1 -PCIEX4_PETP1
differential pair PCIE30_PORT1_TX0: +PCIEX4_PETN0 -PCIEX4_PETP0
differential pair PCIE30_PORT1_TX1: +PCIE30_PORT1_TX1P -PCIEX4_PETN1
differential pair PCIE30_PORT1_TX1: +PCIE30_PORT1_TX1N -PCIE30_PORT1_TX1P
differential pair PCIE30_PORT1_TX0: +PCIE30_PORT1_TX0P -PCIEX4_PETN0
differential pair PCIE30_PORT1_TX0: +PCIE30_PORT1_TX0N -PCIE30_PORT1_TX0P
differential pair PCIE30_PORT1_RX1: +PCIE30_PORT1_RX1N -PCIE30_PORT1_RX1P
differential pair PCIE30_PORT1_RX0: +PCIE30_PORT1_RX0N -PCIE30_PORT1_RX0P
differential pair PCIE30_PORT1_REF_CLK: +PCIE30_PORT1_REF_CLKN -PCIE30_PORT1_REF_CLKP
differential pair PCIE30_PORT0_TX1: +PCIE30_PORT0_TX1P -PETN1
differential pair PCIE30_PORT0_TX1: +PCIE30_PORT0_TX1N -PCIE30_PORT0_TX1P
differential pair PCIE30_PORT0_TX0: +PCIE30_PORT0_TX0P -PETN0
differential pair PCIE30_PORT0_TX0: +PCIE30_PORT0_TX0N -PCIE30_PORT0_TX0P
differential pair PCIE30_PORT0_RX1: +PCIE30_PORT0_RX1N -PCIE30_PORT0_RX1P
differential pair PCIE30_PORT0_RX0: +PCIE30_PORT0_RX0N -PCIE30_PORT0_RX0P
differential pair PCIE30_PORT0_REF_CLK: +PCIE30_PORT0_REF_CLKN -PCIE30_PORT0_REF_CLKP
differential pair PCIE20_2_TX: +PCIE20_2_TXP -PE_TXN
differential pair PCIE20_2_TX: +PCIE20_2_TXN -PCIE20_2_TXP
differential pair PCIE20_2_RX: +PCIE20_2_RXN -PCIE20_2_RXP
differential pair PCIE20_2_REFCLK: +PCIE20_2_REFCLKN -PCIE20_2_REFCLKP
differential pair DP14: +PCIE20_1_TXN -PCIE20_1_TXP
differential pair PCIE20_1_RX: +PCIE20_1_RXN -PCIE20_1_RXP
differential pair PCIE20_1_REFCLK: +PCIE20_1_REFCLKN -PCIE20_1_REFCLKP
differential pair DP2: +N17044768 -USB_HUB_DM4
differential pair DP2: +N17044766 -N17044768
differential pair DP3: +N16844509 -USB_HUB_DM3
differential pair DP3: +N16844471 -N16844509
differential pair PCIE30_PORT1_REF_CLK: +N16810873 -PCIE30_PORT1_REF_CLKN
differential pair PCIE30_PORT1_REF_CLK: +N16810864 -N16810873
differential pair PCIEX4_REF_CLK: +N16810480 -PCIEX4_REF_CLKN
differential pair PCIEX4_REF_CLK: +N16810459 -N16810480
differential pair M2PCIE_REF_CLK: +N16803867 -N16803869
differential pair PCIE30_PORT0_REF_CLK: +N16803772 -PCIE30_PORT0_REF_CLKN
differential pair PCIE30_PORT0_REF_CLK: +N16803735 -N16803772
differential pair DP1: +N16621978 -USB20_HOST1_DM
differential pair DP1: +N16621974 -N16621978
differential pair MIPI_DPHY1_TX_D3: +MIPI_DPHY1_TX_D3N -MIPI_DPHY1_TX_D3P
differential pair MIPI_DPHY1_TX_D2: +MIPI_DPHY1_TX_D2N -MIPI_DPHY1_TX_D2P
differential pair MIPI_DPHY1_TX_D1: +MIPI_DPHY1_TX_D1N -MIPI_DPHY1_TX_D1P
differential pair MIPI_DPHY1_TX_D0: +MIPI_DPHY1_TX_D0N -MIPI_DPHY1_TX_D0P
differential pair MIPI_DPHY1_TX_CLK: +MIPI_DPHY1_TX_CLKN -MIPI_DPHY1_TX_CLKP
differential pair MIPI_DPHY1_RX_D3: +MIPI_DPHY1_RX_D3N -MIPI_DPHY1_RX_D3P
differential pair MIPI_DPHY1_RX_D2: +MIPI_DPHY1_RX_D2N -MIPI_DPHY1_RX_D2P
differential pair MIPI_DPHY1_RX_D1: +MIPI_DPHY1_RX_D1N -MIPI_DPHY1_RX_D1P
differential pair MIPI_DPHY1_RX_D0: +MIPI_DPHY1_RX_D0N -MIPI_DPHY1_RX_D0P
differential pair MIPI_DPHY1_RX_CLK: +MIPI_DPHY1_RX_CLKN -MIPI_DPHY1_RX_CLKP
differential pair MIPI_DPHY0_TX_D3: +MIPI_DPHY0_TX_D3N -MIPI_DPHY0_TX_D3P
differential pair MIPI_DPHY0_TX_D2: +MIPI_DPHY0_TX_D2N -MIPI_DPHY0_TX_D2P
differential pair MIPI_DPHY0_TX_D1: +MIPI_DPHY0_TX_D1N -MIPI_DPHY0_TX_D1P
differential pair MIPI_DPHY0_TX_D0: +MIPI_DPHY0_TX_D0N -MIPI_DPHY0_TX_D0P
differential pair MIPI_DPHY0_TX_CLK: +MIPI_DPHY0_TX_CLKN -MIPI_DPHY0_TX_CLKP
differential pair MIPI_DPHY0_RX_D3: +MIPI_DPHY0_RX_D3N -MIPI_DPHY0_RX_D3P
differential pair MIPI_DPHY0_RX_D2: +MIPI_DPHY0_RX_D2N -MIPI_DPHY0_RX_D2P
differential pair MIPI_DPHY0_RX_D1: +MIPI_DPHY0_RX_D1N -MIPI_DPHY0_RX_D1P
differential pair MIPI_DPHY0_RX_D0: +MIPI_DPHY0_RX_D0N -MIPI_DPHY0_RX_D0P
differential pair MIPI_DPHY0_RX_CLK: +MIPI_DPHY0_RX_CLKN -MIPI_DPHY0_RX_CLKP
differential pair MIPI_CSI1_D3: +MIPI_CSI1_D3N -MIPI_CSI1_D3P
differential pair MIPI_CSI1_D2: +MIPI_CSI1_D2N -MIPI_CSI1_D2P
differential pair MIPI_CSI1_D1: +MIPI_CSI1_D1N -MIPI_CSI1_D1P
differential pair MIPI_CSI1_D0: +MIPI_CSI1_D0N -MIPI_CSI1_D0P
differential pair MIPI_CSI1_CLK1: +MIPI_CSI1_CLK1N -MIPI_CSI1_CLK1P
differential pair MIPI_CSI1_CLK0: +MIPI_CSI1_CLK0N -MIPI_CSI1_CLK0P
differential pair MIPI_CSI0_D3: +MIPI_CSI0_D3N -MIPI_CSI0_D3P
differential pair MIPI_CSI0_D2: +MIPI_CSI0_D2N -MIPI_CSI0_D2P
differential pair MIPI_CSI0_D1: +MIPI_CSI0_D1N -MIPI_CSI0_D1P
differential pair MIPI_CSI0_D0: +MIPI_CSI0_D0N -MIPI_CSI0_D0P
differential pair MIPI_CSI0_CLK1: +MIPI_CSI0_CLK1N -MIPI_CSI0_CLK1P
differential pair MIPI_CSI0_CLK0: +MIPI_CSI0_CLK0N -MIPI_CSI0_CLK0P
differential pair DP18: +MDIP3_PHY1 -MDIP3_PHY1_RJ45
differential pair DP22: +MDIP3_PHY0 -MDIP3_PHY0_RJ45
differential pair DP17: +MDIP2_PHY1 -MDIP2_PHY1_RJ45
differential pair DP21: +MDIP2_PHY0 -MDIP2_PHY0_RJ45
differential pair DP16: +MDIP1_PHY1 -MDIP1_PHY1_RJ45
differential pair DP20: +MDIP1_PHY0 -MDIP1_PHY0_RJ45
differential pair DP15: +MDIP0_PHY1 -MDIP0_PHY1_RJ45
differential pair DP19: +MDIP0_PHY0 -MDIP0_PHY0_RJ45
differential pair DP18: +MDIN3_PHY1_RJ45 -MDIP3_PHY1
differential pair DP18: +MDIN3_PHY1 -MDIN3_PHY1_RJ45
differential pair DP22: +MDIN3_PHY0_RJ45 -MDIP3_PHY0
differential pair DP22: +MDIN3_PHY0 -MDIN3_PHY0_RJ45
differential pair DP17: +MDIN2_PHY1_RJ45 -MDIP2_PHY1
differential pair DP17: +MDIN2_PHY1 -MDIN2_PHY1_RJ45
differential pair DP21: +MDIN2_PHY0_RJ45 -MDIP2_PHY0
differential pair DP21: +MDIN2_PHY0 -MDIN2_PHY0_RJ45
differential pair DP16: +MDIN1_PHY1_RJ45 -MDIP1_PHY1
differential pair DP16: +MDIN1_PHY1 -MDIN1_PHY1_RJ45
differential pair DP20: +MDIN1_PHY0_RJ45 -MDIP1_PHY0
differential pair DP20: +MDIN1_PHY0 -MDIN1_PHY0_RJ45
differential pair DP15: +MDIN0_PHY1_RJ45 -MDIP0_PHY1
differential pair DP15: +MDIN0_PHY1 -MDIN0_PHY1_RJ45
differential pair DP19: +MDIN0_PHY0_RJ45 -MDIP0_PHY0
differential pair DP19: +MDIN0_PHY0 -MDIN0_PHY0_RJ45
differential pair M2PCIE_REF_CLK: +M2PCIE_REF_CLKP -N16803867
differential pair M2PCIE_REF_CLK: +M2PCIE_REF_CLKN -M2PCIE_REF_CLKP
differential pair DIFF_HDMI1_EARC: +HDMI1_EARC- -HDMI1_EARC+
differential pair DIFF_HDMI0_EARC: +HDMI0_EARC- -HDMI0_EARC+
differential pair DIFF_HDMI1_EARC: +HDMI_TX1_SBDP -HDMI1_EARC-
differential pair DIFF_HDMI1_EARC: +HDMI_TX1_SBDN -HDMI_TX1_SBDP
differential pair DIFF_HDMI_TX1_D3: +HDMI_TX1_D3P -HDMI_TX1_D3P_PORT
differential pair DIFF_HDMI_TX1_D3: +HDMI_TX1_D3N_PORT -HDMI_TX1_D3P
differential pair DIFF_HDMI_TX1_D3: +HDMI_TX1_D3N -HDMI_TX1_D3N_PORT
differential pair DIFF_HDMI_TX1_D2: +HDMI_TX1_D2P -HDMI_TX1_D2P_PORT
differential pair DIFF_HDMI_TX1_D2: +HDMI_TX1_D2N_PORT -HDMI_TX1_D2P
differential pair DIFF_HDMI_TX1_D2: +HDMI_TX1_D2N -HDMI_TX1_D2N_PORT
differential pair DIFF_HDMI_TX1_D1: +HDMI_TX1_D1P -HDMI_TX1_D1P_PORT
differential pair DIFF_HDMI_TX1_D1: +HDMI_TX1_D1N_PORT -HDMI_TX1_D1P
differential pair DIFF_HDMI_TX1_D1: +HDMI_TX1_D1N -HDMI_TX1_D1N_PORT
differential pair DIFF_HDMI_TX1_D0: +HDMI_TX1_D0P -HDMI_TX1_D0P_PORT
differential pair DIFF_HDMI_TX1_D0: +HDMI_TX1_D0N_PORT -HDMI_TX1_D0P
differential pair DIFF_HDMI_TX1_D0: +HDMI_TX1_D0N -HDMI_TX1_D0N_PORT
differential pair DIFF_HDMI0_EARC: +HDMI_TX0_SBDP -HDMI0_EARC-
differential pair DIFF_HDMI0_EARC: +HDMI_TX0_SBDN -HDMI_TX0_SBDP
differential pair DIFF_HDMI_TX0_D3: +HDMI_TX0_D3P -HDMI_TX0_D3P_PORT
differential pair DIFF_HDMI_TX0_D3: +HDMI_TX0_D3N_PORT -HDMI_TX0_D3P
differential pair DIFF_HDMI_TX0_D3: +HDMI_TX0_D3N -HDMI_TX0_D3N_PORT
differential pair DIFF_HDMI_TX0_D2: +HDMI_TX0_D2P -HDMI_TX0_D2P_PORT
differential pair DIFF_HDMI_TX0_D2: +HDMI_TX0_D2N_PORT -HDMI_TX0_D2P
differential pair DIFF_HDMI_TX0_D2: +HDMI_TX0_D2N -HDMI_TX0_D2N_PORT
differential pair DIFF_HDMI_TX0_D1: +HDMI_TX0_D1P -HDMI_TX0_D1P_PORT
differential pair DIFF_HDMI_TX0_D1: +HDMI_TX0_D1N_PORT -HDMI_TX0_D1P
differential pair DIFF_HDMI_TX0_D1: +HDMI_TX0_D1N -HDMI_TX0_D1N_PORT
differential pair DIFF_HDMI_TX0_D0: +HDMI_TX0_D0P -HDMI_TX0_D0P_PORT
differential pair DIFF_HDMI_TX0_D0: +HDMI_TX0_D0N_PORT -HDMI_TX0_D0P
differential pair DIFF_HDMI_TX0_D0: +HDMI_TX0_D0N -HDMI_TX0_D0N_PORT
differential pair DIFF_HDMI_RX_CLK: +HDMI_RXCLKN_PORT -HDMI_RXCLKP_PORT
differential pair DIFF_HDMI_RX_D2: +HDMI_RX2N_PORT -HDMI_RX2P_PORT
differential pair DIFF_HDMI_RX_D1: +HDMI_RX1N_PORT -HDMI_RX1P_PORT
differential pair DIFF_HDMI_RX_D0: +HDMI_RX0N_PORT -HDMI_RX0P_PORT
differential pair DIFF_HDMI_RX_D2: +HDMI_RX_D2P -HDMI_RX2N_PORT
differential pair DIFF_HDMI_RX_D2: +HDMI_RX_D2N -HDMI_RX_D2P
differential pair DIFF_HDMI_RX_D1: +HDMI_RX_D1P -HDMI_RX1N_PORT
differential pair DIFF_HDMI_RX_D1: +HDMI_RX_D1N -HDMI_RX_D1P
differential pair DIFF_HDMI_RX_D0: +HDMI_RX_D0P -HDMI_RX0N_PORT
differential pair DIFF_HDMI_RX_D0: +HDMI_RX_D0N -HDMI_RX_D0P
differential pair DIFF_HDMI_RX_CLK: +HDMI_RX_CLKP -HDMI_RXCLKN_PORT
differential pair DIFF_HDMI_RX_CLK: +HDMI_RX_CLKN -HDMI_RX_CLKP
differential pair DP14: +EKEY_PETP0 -PCIE20_1_TXN
differential pair DP14: +EKEY_PETN0 -EKEY_PETP0

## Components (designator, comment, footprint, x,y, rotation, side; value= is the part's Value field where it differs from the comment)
C1 "CAP_NP_C0603_DISCRETE_10UF" C0603#1 445,2925 r180 top
C2 "CAP_NP_C0603_DISCRETE_10UF" C0603#1 605,2925 r0 top
C3 "CAP_NP_C0402_DISCRETE_0.1UF" C0402#1 515,2760 r180 top
C4 "CAP_NP_C0402_DISCRETE_NC" C0402#1 1080,350 r0 top
C5 "CAP_NP_C0402_DISCRETE_NC" C0402#1 795,310 r180 top
C6 "CAP_NP_C0402_DISCRETE_0.1UF" C0402#1 790,1954.37 r90 top
C7 "CAP_NP_C0402_DISCRETE_NC" C0402#1 730,1964.37 r0 bottom
C8 "CAP_NP_C0805_DISCRETE_22UF" C0805 1085,1984.37 r90 top
C9 "CAP_NP_C0402_DISCRETE_10UF" C0402#1 6015,305 r180 top
C10 "CAP_NP_C0402_DISCRETE_0.1UF" C0402#1 6015,560 r180 top
C11 "CAP_NP_C0402_DISCRETE_0.1UF" C0402#1 1085,1984.37 r90 bottom
C12 "CAP_NP_C0805_DISCRETE_22UF" C0805 500,1984.37 r270 top
C13 "CAP_NP_C0402_DISCRETE_0.1UF" C0402#1 575,1984.37 r270 top
C14 "CAP_NP_C0402_DISCRETE_0.1UF" C0402#1 790,1729.37 r90 top
C15 "CAP_NP_C0402_DISCRETE_0.1UF" C0402#1 705,350 r180 top
C16 "CAP_NP_C0402_DISCRETE_0.22UF" C0402#1 810,990.04 r0 top
C17 "CAP_NP_C0603_DISCRETE_10UF" C0603#1 505,984.37 r90 top
C18 "CAP_NP_C0603_DISCRETE_10UF" C0603#1 575,985.04 r90 top
C19 "CAP_NP_C0402_DISCRETE_0.1UF" C0402#1 575,855.04 r270 top
C20 "CAP_NP_C0402_DISCRETE_NC" C0402#1 840,995.04 r270 bottom
C21 "CAP_NP_C0805_DISCRETE_47UF" C0805 935,540 r180 top
C22 "CAP_NP_C0805_DISCRETE_47UF" C0805 935,635 r180 top
C23 "CAP_NP_C0603_DISCRETE_22UF" C0603#1 1075,540 r0 top
C24 "CAP_NP_C0402_DISCRETE_0.1UF" C0402#1 1070,635 r0 top
C25 "CAP_NP_C0402_DISCRETE_1UF" C0402#1 720,884.37 r0 bottom
C26 "CAP_NP_C0402_DISCRETE_0.1UF" C0402#2 590,865.04 r0 bottom
C27 "CAP_NP_C0402_DISCRETE_0.1UF" C0402#1 695,714.37 r180 top
C28 "CAP_NP_C0402_DISCRETE_0.1UF" C0402#1 505,310 r0 top
C29 "CAP_NP_C0402_DISCRETE_0.1UF" C0402#1 2819,2700 r90 bottom
C30 "CAP_NP_C0402_DISCRETE_0.1UF" C0402#1 2780,2700 r90 bottom
C31 "CAP_NP_C0402_DISCRETE_0.1UF" C0402#1 3030,2585 r0 top
C32 "CAP_NP_C0402_DISCRETE_4.7UF" C0402#1 3030,2545 r0 top
C33 "CAP_NP_C0402_DISCRETE_18PF" C0402#1 2990,2910 r180 top
C34 "CAP_NP_C0402_DISCRETE_18PF" C0402#1 3010,2810 r270 top
C35 "CAP_NP_C0402_DISCRETE_0.1UF" C0402#1 2990,2895 r0 bottom
C36 "CAP_NP_C0805_DISCRETE_1NF" C0805 2850,3374.37 r90 bottom
C37 "CAP_NP_C0402_DISCRETE_0.1UF" C0402#1 2685,2855 r0 bottom
C38 "CAP_NP_C0402_DISCRETE_0.1UF" C0402#1 2699,2700 r90 bottom
C39 "CAP_NP_C0402_DISCRETE_0.1UF" C0402#1 3010,2730 r90 top
C40 "CAP_NP_C0402_DISCRETE_0.1UF" C0402#1 2819,2875 r270 bottom
C41 "CAP_NP_C0402_DISCRETE_0.1UF" C0402#2 2879,2815 r0 bottom
C42 "CAP_NP_C0402_DISCRETE_0.1UF" C0402#1 3050,2730 r90 top
C43 "CAP_NP_C0402_DISCRETE_0.1UF" C0402#1 2749,2875 r270 bottom
C44 "CAP_NP_C0402_DISCRETE_0.1UF" C0402#2 2879,2895 r0 bottom
C45 "CAP_NP_C0402_DISCRETE_0.1UF" C0402#1 2990,2960 r0 top
C46 "CAP_NP_C0402_DISCRETE_0.1UF" C0402#1 2684,2895 r0 bottom
C47 "CAP_NP_C0402_DISCRETE_0.1UF" C0402#1 3110,2625 r180 top
C48 "CAP_NP_C0402_DISCRETE_0.1UF" C0402#1 3110,2710 r180 top
C49 "CAP_NP_C0402_DISCRETE_0.1UF" C0402#1 3110,2665 r180 top
C50 "CAP_NP_C0402_DISCRETE_0.1UF" C0402#1 2054.59,2705 r90 bottom
C51 "CAP_NP_C0402_DISCRETE_0.1UF" C0402#1 2094.59,2705 r90 bottom
C52 "CAP_NP_C0402_DISCRETE_0.1UF" C0402#1 2330,2585 r0 top
C53 "CAP_NP_C0402_DISCRETE_4.7UF" C0402#1 2330,2545 r0 top
C54 "CAP_NP_C0402_DISCRETE_18PF" C0402#1 2290,2910 r180 top
C55 "CAP_NP_C0402_DISCRETE_18PF" C0402#1 2310,2810 r270 top
C56 "CAP_NP_C0402_DISCRETE_0.1UF" C0402#1 2435,3099.37 r90 bottom
C57 "CAP_NP_C0805_DISCRETE_1NF" C0805 2115,3369.37 r90 bottom
C58 "CAP_NP_C0402_DISCRETE_0.1UF" C0402#1 1960,2855 r0 bottom
C59 "CAP_NP_C0402_DISCRETE_0.1UF" C0402#1 2445,2665 r0 top
C60 "CAP_NP_C0402_DISCRETE_0.1UF" C0402#1 2350,2730 r90 top
C61 "CAP_NP_C0402_DISCRETE_0.1UF" C0402#1 1974.59,2705 r90 bottom
C62 "CAP_NP_C0402_DISCRETE_0.1UF" C0402#1 2024.59,2875 r270 bottom
C63 "CAP_NP_C0402_DISCRETE_0.1UF" C0402#1 2094.59,2875 r270 bottom
C64 "CAP_NP_C0402_DISCRETE_0.1UF" C0402#2 2154.59,2815 r0 bottom
C65 "CAP_NP_C0402_DISCRETE_0.1UF" C0402#1 2310,2730 r90 top
C66 "CAP_NP_C0402_DISCRETE_0.1UF" C0402#1 1959.59,2895 r0 bottom
C67 "CAP_NP_C0402_DISCRETE_0.1UF" C0402#1 2290,2960 r0 top
C68 "CAP_NP_C0402_DISCRETE_0.1UF" C0402#2 2154.59,2895 r0 bottom
C69 "CAP_NP_C0402_DISCRETE_0.1UF" C0402#1 2100,2565 r270 top
C70 "CAP_NP_C0402_DISCRETE_0.1UF" C0402#1 2155,2630 r0 bottom
C71 "CAP_NP_C0402_DISCRETE_0.1UF" C0402#1 2135,2570 r270 bottom
C72 "CAP_NP_C0402_DISCRETE_10UF" C0402#1 745,3225 r180 top
C73 "CAP_NP_C0402_DISCRETE_0.1UF" C0402#1 825,3225 r0 top
C74 "CAP_NP_C0402_DISCRETE_0.1UF" C0402#1 675,3120 r270 top
C75 "CAP_NP_C0402_DISCRETE_0.1UF" C0402#1 4970,2974.37 r270 bottom
C76 "CAP_NP_C0402_DISCRETE_0.1UF" C0402#1 5010,2974.37 r270 bottom
C77 "CAP_NP_C0402_DISCRETE_220PF" C0402#1 780,3225 r0 bottom
C78 "CAP_NP_C0402_DISCRETE_220PF" C0402#2 785,3155 r0 bottom
C79 "CAP_NP_C0402_DISCRETE_0.1UF" C0402#1 1130,3334.37 r270 top
C80 "CAP_NP_C0402_DISCRETE_0.1UF" C0402#1 1090,3334.37 r270 top
C81 "CAP_NP_C0402_DISCRETE_1UF" C0402#1 780,3085 r0 bottom
C82 "CAP_NP_C0402_DISCRETE_0.1UF" C0402#1 870,3334.37 r270 top
C83 "CAP_NP_C0402_DISCRETE_0.1UF" C0402#1 830,3334.37 r270 top
C84 "CAP_NP_C0402_DISCRETE_0.1UF" C0402#1 915,3304.37 r270 bottom
C85 "CAP_NP_C0402_DISCRETE_0.1UF" C0402#1 875,3304.37 r270 bottom
C86 "CAP_NP_C0402_DISCRETE_0.1UF" C0402#1 675,2980 r270 bottom
C87 "CAP_NP_C0402_DISCRETE_10UF" C0402#1 617,3260.37 r0 bottom
C88 "CAP_NP_C0402_DISCRETE_0.1UF" C0402#1 617,3220.37 r0 bottom
C89 "CAP_NP_C0402_DISCRETE_0.1UF" C0402#2 4665,3689.37 r0 bottom
C90 "CAP_NP_C0402_DISCRETE_10UF" C0402#2 4770,3564.37 r0 bottom
C91 "CAP_NP_C0402_DISCRETE_0.1UF" C0402#2 4770,3524.37 r0 bottom
C92 "CAP_NP_C0402_DISCRETE_1UF" C0402#1 5740,3649.37 r0 bottom
C93 "CAP_NP_C0402_DISCRETE_0.1UF" C0402#1 5345,2744.37 r90 bottom
C94 "CAP_NP_C0402_DISCRETE_4.7UF" C0402#1 5425,2744.37 r270 bottom
C95 "CAP_NP_C0402_DISCRETE_0.1UF" C0402#1 5505,2764.37 r180 top
C96 "CAP_NP_C0402_DISCRETE_0.1UF" C0402#1 5625,2764.37 r180 top
C97 "CAP_NP_C0402_DISCRETE_1UF" C0402#1 5740,3689.37 r0 bottom
C98 "CAP_NP_C0402_DISCRETE_0.1UF" C0402#1 5360,2809.37 r180 top
C99 "CAP_NP_C0402_DISCRETE_0.1UF" C0402#2 5440,3669.37 r0 bottom
C100 "CAP_NP_C0402_DISCRETE_10UF" C0402#1 5640,3669.37 r90 bottom
C101 "CAP_NP_C0402_DISCRETE_0.1UF" C0402#1 5680,3669.37 r90 bottom
C102 "CAP_NP_C0402_DISCRETE_NC" C0402#1 5735,2859.37 r270 top
C103 "CAP_NP_C0402_DISCRETE_NC" C0402#1 5735,2939.37 r90 top
C104 "CAP_NP_C0402_DISCRETE_0.1UF" C0402#1 6395,3559.37 r270 top
C105 "CAP_NP_C0402_DISCRETE_4.7UF" C0402#1 6440,3559.37 r270 top
C106 "CAP_NP_C0402_DISCRETE_0.1UF" C0402#1 975,2640 r0 bottom
C107 "CAP_NP_C0402_DISCRETE_4.7UF" C0402#1 975,2600 r0 bottom
C108 "CAP_NP_C0402_DISCRETE_0.1UF" C0402#1 745,2730 r0 bottom
C109 "CAP_NP_C0402_DISCRETE_0.1UF" C0402#2 855,2600 r0 bottom
C110 "CAP_NP_C0402_DISCRETE_4.7UF" C0402#2 855,2640 r0 bottom
C111 "CAP_NP_C0402_DISCRETE_10UF" C0402#1 1395,3564.37 r0 bottom
C112 "CAP_NP_C0402_DISCRETE_1UF" C0402#1 765,2914.37 r90 top
C113 "CAP_NP_C0402_DISCRETE_1UF" C0402#1 805,2914.37 r90 top
C114 "CAP_NP_C0402_DISCRETE_0.1UF" C0402#1 745,2690 r0 bottom
C115 "CAP_NP_C0402_DISCRETE_1UF" C0402#1 845,2914.37 r90 top
C116 "CAP_NP_C0402_DISCRETE_270PF" C0402#1 1490,3659.37 r0 bottom
C117 "CAP_NP_C0402_DISCRETE_1UF" C0402#1 885,2914.37 r90 top
C118 "CAP_NP_C0402_DISCRETE_10UF" C0402#2 855,2765 r0 bottom
C119 "CAP_NP_C0402_DISCRETE_10UF" C0402#1 875,2705 r270 bottom
C120 "CAP_NP_C0402_DISCRETE_10UF" C0402#1 765,2620 r90 bottom
C121 "CAP_NP_C0402_DISCRETE_NC" C0402#1 1395,3619.37 r0 bottom
C122 "CAP_NP_C0603_DISCRETE_47UF" C0603#1 1480,3314.37 r0 bottom
C123 "CAP_NP_C0402_DISCRETE_10UF" C0402#1 730,2540 r0 bottom
C124 "CAP_NP_C0402_DISCRETE_10UF" C0402#2 855,2540 r0 bottom
C125 "CAP_NP_C0402_DISCRETE_4.7UF" C0402#1 75,3234.37 r90 bottom
C126 "CAP_NP_C0402_DISCRETE_100PF" C0402#1 135,3249.37 r0 top
C127 "CAP_NP_C0402_DISCRETE_0.1UF" C0402#1 6240,1945 r180 top
C128 "CAP_NP_C0402_DISCRETE_NC" C0402#2 6220,1965 r0 bottom
C129 "CAP_NP_C0603_DISCRETE_22UF" C0603#1 6220,2229.37 r180 top
C130 "CAP_NP_C0402_DISCRETE_0.1UF" C0402#2 6220,2240 r0 bottom
C131 "CAP_NP_C0402_DISCRETE_0.22UF" C0402#1 3782,2774.37 r90 top
C132 "CAP_NP_C0402_DISCRETE_0.22UF" C0402#1 3742,2774.37 r90 top
C133 "CAP_NP_C0402_DISCRETE_0.22UF" C0402#1 3694,2774.37 r90 top
C134 "CAP_NP_C0402_DISCRETE_0.22UF" C0402#1 3654,2774.37 r90 top
C135 "CAP_NP_C0402_DISCRETE_0.22UF" C0402#1 3605,2774.37 r90 top
C136 "CAP_NP_C0402_DISCRETE_0.22UF" C0402#1 3565,2774.37 r90 top
C137 "CAP_NP_C0402_DISCRETE_0.22UF" C0402#1 3515,2774.37 r90 top
C138 "CAP_NP_C0402_DISCRETE_0.22UF" C0402#1 3475,2774.37 r90 top
C139 "CAP_NP_C0402_DISCRETE_1UF" C0402#1 3420,2774.37 r90 top
C140 "CAP_NP_C0402_DISCRETE_1UF" C0402#1 3380,2774.37 r90 top
C141 "CAP_NP_C0402_DISCRETE_1UF" C0402#2 3390,3709.37 r0 bottom
C142 "CAP_NP_C0402_DISCRETE_100PF" C0402#1 3580,2565 r270 bottom
C143 "CAP_NP_C0402_DISCRETE_0.22UF" C0402#1 4224,2774.37 r90 top
C144 "CAP_NP_C0402_DISCRETE_0.22UF" C0402#1 4184,2774.37 r90 top
C145 "CAP_NP_C0402_DISCRETE_0.22UF" C0402#1 4135,2774.37 r90 top
C146 "CAP_NP_C0402_DISCRETE_0.22UF" C0402#1 4095,2774.37 r90 top
C147 "CAP_NP_C0402_DISCRETE_0.22UF" C0402#1 4047,2774.37 r90 top
C148 "CAP_NP_C0402_DISCRETE_0.22UF" C0402#1 4007,2774.37 r90 top
C149 "CAP_NP_C0402_DISCRETE_0.22UF" C0402#1 3959,2774.37 r90 top
C150 "CAP_NP_C0402_DISCRETE_0.22UF" C0402#1 3919,2774.37 r90 top
C151 "CAP_NP_C0402_DISCRETE_1UF" C0402#1 3870,2774.37 r90 top
C152 "CAP_NP_C0402_DISCRETE_1UF" C0402#1 3830,2774.37 r90 top
C153 "CAP_NP_C0402_DISCRETE_1UF" C0402#2 3740,3709.37 r0 bottom
C154 "CAP_NP_C0402_DISCRETE_100PF" C0402#1 4695,2564.37 r270 bottom
C155 "CAP_NP_C0402_DISCRETE_1UF" C0402#1 4520,3014.37 r0 bottom
C156 "CAP_NP_C0402_DISCRETE_0.1UF" C0402#1 6025,2555 r180 top
C157 "CAP_NP_C0402_DISCRETE_NC" C0402#2 6005,2575 r0 bottom
C158 "CAP_NP_C0603_DISCRETE_22UF" C0603#1 6005,2840 r0 top
C159 "CAP_NP_C0402_DISCRETE_0.1UF" C0402#1 6005,2890 r0 top
C160 "CAP_NP_C0603_DISCRETE_22UF" C0603#1 6005,2360 r0 bottom
C161 "CAP_NP_C0402_DISCRETE_0.1UF" C0402#1 6000,2365 r0 top
C162 "CAP_NP_C0402_DISCRETE_1UF" C0402#1 4610,1450 r0 bottom
C163 "CAP_NP_C0402_DISCRETE_0.1UF" C0402#1 4610,1449.37 r0 top
C164 "CAP_NP_C0402_DISCRETE_18PF" C0402#1 4610,1539.37 r0 top
C165 "CAP_NP_C0402_DISCRETE_18PF" C0402#1 4610,1629.37 r180 top
C166 "CAP_NP_C0402_DISCRETE_0.1UF" C0402#1 4240,1515 r270 bottom
C167 "CAP_NP_C0402_DISCRETE_1UF" C0402#1 4280,1515 r270 bottom
C168 "CAP_NP_C0402_DISCRETE_4.7UF" C0402#1 4240,1595 r270 bottom
C169 "CAP_NP_C0402_DISCRETE_0.1UF" C0402#1 6205,3005 r0 top
C170 "CAP_NP_C0402_DISCRETE_0.1UF" C0402#1 6005,3005 r0 top
C171 "CAP_NP_C0402_DISCRETE_0.1UF" C0402#1 6005,2965 r0 top
C172 "CAP_NP_C0402_DISCRETE_0.1UF" C0402#2 6620,3190 r0 bottom
C173 "CAP_NP_C0402_DISCRETE_0.1UF" C0402#2 6620,3150 r0 bottom
C174 "CAP_NP_C0402_DISCRETE_0.1UF" C0402#2 6620,3110 r0 bottom
C175 "CAP_NP_C0402_DISCRETE_0.22UF" C0402#1 6300,3280 r90 bottom
C176 "CAP_NP_C0402_DISCRETE_0.22UF" C0402#1 6340,3280 r90 bottom
C177 "CAP_NP_C0402_DISCRETE_0.22UF" C0402#1 6420,3280 r90 bottom
C178 "CAP_NP_C0402_DISCRETE_0.22UF" C0402#1 6460,3280 r90 bottom
C179 "CAP_NP_C0402_DISCRETE_0.1UF" C0402#1 790,1489.37 r90 top
C180 "CAP_NP_C0603_DISCRETE_22UF" C0603#1 1085,1509.37 r90 top
C181 "CAP_NP_C0402_DISCRETE_0.1UF" C0402#1 6205,2965 r0 top
C182 "CAP_NP_C0402_DISCRETE_0.1UF" C0402#1 6105,2985 r270 top
C183 "CAP_NP_C0402_DISCRETE_0.1UF" C0402#1 6145,2985 r270 top
C184 "CAP_NP_C0402_DISCRETE_4.7UF" C0402#1 4960,1065 r90 bottom
C185 "CAP_NP_C0402_DISCRETE_0.1UF" C0402#1 4960,1065 r90 top
C186 "CAP_NP_C0402_DISCRETE_4.7UF" C0402#1 4960,1145 r270 bottom
C187 "CAP_NP_C0402_DISCRETE_0.1UF" C0402#1 4960,1145 r270 top
C188 "CAP_NP_C0402_DISCRETE_NC" C0402#1 5050,1145 r270 bottom
C189 "CAP_NP_C0402_DISCRETE_0.22UF" C0402#1 435,1439.37 r180 top
C190 "CAP_NP_C0402_DISCRETE_0.22UF" C0402#1 435,1399.37 r180 top
C191 "CAP_NP_C0402_DISCRETE_0.22UF" C0402#1 435,1279.37 r180 top
C192 "CAP_NP_C0402_DISCRETE_0.22UF" C0402#1 435,1239.37 r180 top
C193 "CAP_NP_C0402_DISCRETE_0.1UF" C0402#1 1085,1509.37 r90 bottom
C194 "CAP_NP_C0402_DISCRETE_NC" C0402#1 735,1504.37 r0 bottom
C195 "CAP_NP_C0603_DISCRETE_22UF" C0603#1 505,1519.37 r270 top
C196 "CAP_NP_C0402_DISCRETE_0.1UF" C0402#1 575,1519.37 r270 top
C197 "CAP_NP_C0603_DISCRETE_22UF" C0603#1 995,1319.37 r90 top
C198 "CAP_NP_C0402_DISCRETE_0.1UF" C0402#1 1015,1309.37 r90 bottom
C199 "CAP_NP_C0402_DISCRETE_0.1UF" C0402#1 6030,1945 r0 top
C200 "CAP_NP_C0402_DISCRETE_NC" C0402#1 6010,1965 r0 bottom
C201 "CAP_NP_C0603_DISCRETE_22UF" C0603#1 6005,2300 r0 bottom
C202 "CAP_NP_C0402_DISCRETE_1UF" C0402#1 6005,2255 r0 bottom
C203 "CAP_NP_C0402_DISCRETE_0.1UF" C0402#1 6005,2215 r0 bottom
C204 "CAP_NP_C0603_DISCRETE_22UF" C0603#1 6010,1735 r0 bottom
C205 "CAP_NP_C0402_DISCRETE_10UF" C0402#1 6015,1715 r0 top
C206 "CAP_NP_C0402_DISCRETE_0.1UF" C0402#1 6015,1755 r0 top
C207 "CAP_NP_C0402_DISCRETE_33PF" C0402#2 5960,745 r0 bottom
C208 "CAP_NP_C0402_DISCRETE_33PF" C0402#2 5960,790 r0 bottom
C209 "CAP_NP_C0402_DISCRETE_33PF" C0402#2 5960,835 r0 bottom
C210 "CAP_NP_C1206_DISCRETE_47UF" C1206 1260,2835 r0 top
C211 "CAP_NP_C1206_DISCRETE_47UF" C1206 1260,2615 r0 top
C212 "CAP_NP_C0402_DISCRETE_10UF" C0402#1 5405,1554.37 r90 bottom
C213 "CAP_NP_C0402_DISCRETE_0.1UF" C0402#1 5450,1554.37 r90 bottom
C214 "CAP_NP_C0402_DISCRETE_0.1UF" C0402#1 4700,2079.37 r90 top
C215 "CAP_NP_C0402_DISCRETE_0.1UF" C0402#1 4660,2079.37 r90 top
C216 "CAP_NP_C0402_DISCRETE_0.1UF" C0402#1 4770,779.37 r0 bottom
C217 "CAP_NP_C0402_DISCRETE_0.1UF" C0402#1 4770,839.37 r0 bottom
C218 "CAP_NP_C1206_DISCRETE_47UF" C1206 1260,2725 r0 top
C219 "CAP_NP_C0805_DISCRETE_22UF" C0805 1260,2945 r0 top
C220 "CAP_NP_C0402_DISCRETE_0.1UF" C0402#1 4760,2079.37 r270 top
C221 "CAP_NP_C0402_DISCRETE_0.1UF" C0402#1 5200,2079.37 r270 top
C222 "CAP_NP_C0402_DISCRETE_0.1UF" C0402#1 5000,2649.37 r0 bottom
C223 "CAP_NP_C0402_DISCRETE_0.1UF" C0402#1 5673.23,2079.37 r270 top
C224 "CAP_NP_C0402_DISCRETE_0.1UF" C0402#1 490,2545 r0 top
C225 "CAP_NP_C0402_DISCRETE_NC" C0402#1 480,2574.37 r270 bottom
C226 "CAP_NP_C0805_DISCRETE_22UF" C0805 695,2420 r90 top
C227 "CAP_NP_C0402_DISCRETE_0.1UF" C0402#1 765,2420 r90 top
C228 "CAP_NP_C0805_DISCRETE_22UF" C0805 485,2825 r180 top
C229 "CAP_NP_C0402_DISCRETE_0.1UF" C0402#1 515,2720 r180 top
C230 "CAP_NP_C0805_DISCRETE_22UF" C0805 1085,1754.37 r90 top
C231 "CAP_NP_C0402_DISCRETE_0.1UF" C0402#1 1085,1739.37 r90 bottom
C232 "CAP_NP_C0402_DISCRETE_NC" C0402#1 740,1739.37 r0 bottom
C233 "CAP_NP_C0805_DISCRETE_22UF" C0805 500,1749.37 r270 top
C234 "CAP_NP_C0402_DISCRETE_0.1UF" C0402#1 575,1749.37 r270 top
C235 "CAP_NP_C0402_DISCRETE_0.1UF" C0402#1 195,420 r270 top
C236 "CAP_NP_C0402_DISCRETE_0.1UF" C0402#1 295,420 r180 top
C237 "CAP_NP_C0402_DISCRETE_0.1UF" C0402#1 4820,1300 r90 top
C238 "CAP_NP_C0402_DISCRETE_10UF" C0402#1 4640,1305 r270 top
C239 "CAP_NP_C0402_DISCRETE_0.1UF" C0402#2 660,1739.37 r0 bottom
C240 "CAP_NP_C0402_DISCRETE_18PF" C0402#1 4820,1144.37 r90 top
C241 "CAP_NP_C0402_DISCRETE_18PF" C0402#1 4820,1064.37 r270 top
C242 "CAP_NP_C0402_DISCRETE_0.1UF" C0402#1 5770,824.37 r90 bottom
C243 "CAP_NP_C0402_DISCRETE_0.1UF" C0402#1 5465,824.37 r90 bottom
C244 "CAP_NP_C0402_DISCRETE_0.1UF" C0402#1 5141.57,599.37 r0 bottom
C245 "CAP_NP_C0402_DISCRETE_0.1UF" C0402#2 5171.57,419.37 r0 bottom
C246 "CAP_NP_C0402_DISCRETE_0.1UF" C0402#1 5391.57,379.37 r0 bottom
C247 "CAP_NP_C0402_DISCRETE_0.1UF" C0402#2 5171.57,379.37 r0 bottom
C248 "CAP_NP_C0402_DISCRETE_0.1UF" C0402#2 5291.57,379.37 r0 bottom
C249 "CAP_NP_C0603_DISCRETE_22UF" C0603#1 6220,1735 r0 bottom
C250 "CAP_NP_C0402_DISCRETE_0.1UF" C0402#1 6220,1755 r0 top
C251 "CAP_NP_C0402_DISCRETE_0.1UF" C0402#1 5335,2114.37 r90 bottom
C252 "CAP_NP_C0402_DISCRETE_0.1UF" C0402#1 5295,2114.37 r90 bottom
C253 "CAP_NP_C0402_DISCRETE_0.1UF" C0402#1 5145,3669.37 r270 bottom
C254 "CAP_NP_C0402_DISCRETE_10UF" C0402#1 817.63,2253 r270 top
C255 "CAP_NP_C0402_DISCRETE_0.1UF" C0402#1 857.63,2253 r270 top
C256 "CAP_NP_C0402_DISCRETE_10UF" C0402#1 492,3260.37 r0 bottom
C257 "CAP_NP_C0402_DISCRETE_0.1UF" C0402#1 492,3220.37 r0 bottom
C258 "CAP_NP_C0402_DISCRETE_0.1UF" C0402#1 1090,2195 r0 top
C259 "CAP_NP_C0402_DISCRETE_0.1UF" C0402#1 550,2980 r270 bottom
C260 "CAP_NP_C0402_DISCRETE_10UF" C0402#1 367,3260.37 r0 bottom
C261 "CAP_NP_C0402_DISCRETE_0.1UF" C0402#1 367,3220.37 r0 bottom
C262 "CAP_NP_C0402_DISCRETE_0.1UF" C0402#1 425,2980 r270 bottom
C263 "CAP_NP_C0402_DISCRETE_10UF" C0402#1 477.63,2253 r270 top
C264 "CAP_NP_C0402_DISCRETE_0.1UF" C0402#1 517.63,2253 r270 top
C265 "CAP_NP_C0402_DISCRETE_0.1UF" C0402#1 750,2195 r0 top
C266 "CAP_NP_C0402_DISCRETE_10UF" C0402#1 6460,2420 r270 bottom
C267 "CAP_NP_C0402_DISCRETE_10UF" C0402#1 6460,2985 r90 top
C268 "CAP_NP_C0402_DISCRETE_0.1UF" C0402#1 6440,2925 r180 top
C269 "CAP_NP_C0402_DISCRETE_0.1UF" C0402#2 6440,2480 r0 bottom
C270 "CAP_NP_C0402_DISCRETE_10UF" C0402#1 6460,2300 r90 top
C271 "CAP_NP_C0402_DISCRETE_0.1UF" C0402#1 6440,2240 r180 top
C272 "CAP_NP_C0402_DISCRETE_10UF" C0402#1 6460,1735 r270 bottom
C273 "CAP_NP_C0402_DISCRETE_0.1UF" C0402#2 6440,1795 r0 bottom
C274 "CAP_NP_C0402_DISCRETE_10UF" C0402#1 6460,1615 r90 top
C275 "CAP_NP_C0402_DISCRETE_0.1UF" C0402#1 6440,1555 r180 top
C276 "CAP_NP_C0402_DISCRETE_10UF" C0402#1 6460,1045 r270 bottom
C277 "CAP_NP_C0402_DISCRETE_0.1UF" C0402#2 6440,1105 r0 bottom
C278 "CAP_NP_C0402_DISCRETE_0.1UF" C0402#1 1035,2860 r180 top
C279 "CAP_NP_C0402_DISCRETE_0.1UF" C0402#1 1090,2445 r0 top
C280 "CAP_NP_C0805_DISCRETE_22UF" C0805 695,634.37 r0 top
C281 "CAP_NP_C0805_DISCRETE_22UF" C0805 695,539.37 r0 top
C282 "CAP_NP_C0402_DISCRETE_0.1UF" C0402#1 695,469.37 r0 top
C283 "CAP_NP_C0402_DISCRETE_0.1UF" C0402#1 790,1109.37 r90 top
C284 "CAP_NP_C0402_DISCRETE_0.1UF" C0402#1 4985,3669.37 r270 bottom
C285 "CAP_NP_C0402_DISCRETE_10UF" C0402#2 4905,3564.37 r0 bottom
C286 "CAP_NP_C0402_DISCRETE_0.1UF" C0402#2 4905,3524.37 r0 bottom
C287 "CAP_NP_C0603_DISCRETE_47UF" C0603#2 1360,3314.37 r0 bottom
C288 "CAP_NP_C0402_DISCRETE_0.1UF" C0402#2 1610,3620 r0 bottom
C289 "CAP_NP_C0402_DISCRETE_0.1UF" C0402#1 1395,3524.37 r0 bottom
C290 "CAP_NP_C0402_DISCRETE_NC" C0402#1 730,1119.37 r0 bottom
C291 "CAP_NP_C0603_DISCRETE_22UF" C0603#1 1085,1124.37 r90 top
C292 "CAP_NP_C0402_DISCRETE_0.1UF" C0402#1 1090,1129.37 r90 bottom
C293 "CAP_NP_C0603_DISCRETE_22UF" C0603#1 505,1134.37 r270 top
C294 "CAP_NP_C0402_DISCRETE_0.1UF" C0402#1 575,1134.37 r270 top
C295 "CAP_NP_C0402_DISCRETE_10NF" C0402#1 2715,325 r270 top
C296 "CAP_NP_C0402_DISCRETE_10NF" C0402#1 2755,325 r270 top
C297 "CAP_NP_C0402_DISCRETE_10NF" C0402#1 2675,325 r270 top
C298 "CAP_NP_C0402_DISCRETE_10NF" C0402#1 2635,325 r270 top
C299 "CAP_NP_C0402_DISCRETE_0.1UF" C0402#1 1035,2500 r0 bottom
C300 "CAP_NP_C0402_DISCRETE_1NF" C0402#1 945,2975 r180 top
C301 "CAP_NP_C0402_DISCRETE_1NF" C0402#1 1120,2975 r0 top
C302 "CAP_NP_C0402_DISCRETE_1UF" C0402#1 1010,2515 r270 top
C303 "CAP_NP_C1206_DISCRETE_47UF" C1206 1705,2645 r0 top
C304 "CAP_NP_C1206_DISCRETE_47UF" C1206 1705,2745 r0 top
C305 "CAP_NP_C1206_DISCRETE_47UF" C1206 1705,2845 r0 top
C306 "CAP_NP_C0805_DISCRETE_22UF" C0805 1705,2945 r0 top
C307 "CAP_NP_C0402_DISCRETE_0.1UF" C0402#1 1480,2855 r180 top
C308 "CAP_NP_C0402_DISCRETE_0.1UF" C0402#1 1555,2420 r90 top
C309 "CAP_NP_C0402_DISCRETE_0.1UF" C0402#1 1505,2420 r90 top
C310 "CAP_NP_C0402_DISCRETE_1NF" C0402#1 1395,2975 r180 top
C311 "CAP_NP_C0402_DISCRETE_1NF" C0402#1 1565,2975 r0 top
C312 "CAP_NP_C0402_DISCRETE_1UF" C0402#1 1455,2515 r270 top
C313 "CAP_NP_C0402_DISCRETE_0.1UF" C0402#1 5090,779.37 r0 bottom
C314 "CAP_NP_C0402_DISCRETE_0.1UF" C0402#1 5090,839.37 r0 bottom
C315 "CAP_CASE-B_3528_220UF" CASE-B_3528 6005,2270 r0 top
C316 "CAP_NP_C0402_DISCRETE_NC" C0402#1 4705,3030 r180 top
D1 "DIODE BI-DIR TRIG_SMA_CA_SMAJ13" SMA_CA 600,3110 r270 top
D2 "DIODE BI-DIR TRIG_ESD0402_D23_1" ESD0402#1 1080,310 r180 top
D3 "DIODE BI-DIR TRIG_ESD0402_D23_1" ESD0402#1 890,310 r180 top
D4 "DIODE BI-DIR TRIG_ESD0402_D23_1" ESD0402#1 705,310 r0 top
D5 "DIODE BI-DIR TRIG_R0201_D1250-5" R0201#1 3472,2830 r0 top
D6 "DIODE BI-DIR TRIG_ESD0402_D23_1" ESD0402#1 425,310 r0 top
D7 "DIODE_SCHTKY_SOD523_IC_RB521S-3" SOD523 1695,2855 r0 bottom
D8 "DIODE BI-DIR TRIG_ESD0402_D2315" ESD0402#1 1050,3414.37 r90 top
D9 "DIODE BI-DIR TRIG_ESD0402_D2315" ESD0402#1 990,3414.37 r90 top
D10 "DIODE BI-DIR TRIG_ESD0402_D2315" ESD0402#2 1105,3499.37 r0 bottom
D11 "DIODE BI-DIR TRIG_ESD0402_D2315" ESD0402#1 975,3559.37 r0 bottom
D12 "DIODE BI-DIR TRIG_ESD0402_D2315" ESD0402#2 935,3444.37 r0 bottom
D13 "DIODE BI-DIR TRIG_ESD0402_D2315" ESD0402#1 855,3444.37 r0 bottom
D14 "DIODE BI-DIR TRIG_R0201_D1250-5" R0201#1 3517,2830 r180 top
D15 "DIODE_SOD-123_1N4148W" SOD-123#1 4040,1305 r270 top
D16 "DIODE BI-DIR TRIG_ESD0402_D2315" ESD0402#1 6115,355 r0 top
D17 "DIODE BI-DIR TRIG_ESD0402_D2315" ESD0402#1 6115,405 r0 top
D18 "DIODE BI-DIR TRIG_ESD0402_D2315" ESD0402#1 6115,455 r0 top
D19 "DIODE BI-DIR TRIG_ESD0402_D2315" ESD0402#1 6115,505 r0 top
D20 "DIODE BI-DIR TRIG_ESD0402_D2315" ESD0402#1 6115,610 r0 top
D21 "DIODE BI-DIR TRIG_ESD0402_D2315" ESD0402#1 6115,660 r0 top
D22 "DIODE BI-DIR TRIG_ESD0402_D2315" ESD0402#1 6115,710 r0 top
D23 "DIODE BI-DIR TRIG_ESD0402_D23_1" ESD0402#1 6115,559.29 r180 top
D24 "DIODE BI-DIR TRIG_ESD0402_D23_1" ESD0402#2 2170,270 r0 bottom
D25 "DIODE BI-DIR TRIG_ESD0402_D23_1" ESD0402#2 2090,270 r0 bottom
D26 "DIODE_SCHTKY_SOD-123_IC_1N5819W" SOD-123#2 3535,3689.37 r0 bottom
D27 "DIODE BI-DIR TRIG_R0201_D1250-5" R0201#1 3377,2830 r0 top
D28 "DIODE BI-DIR TRIG_R0201_D1250-5" R0201#1 3430,2813.73 r90 bottom
D29 "DIODE BI-DIR TRIG_R0201_D1250-5" R0201#1 3340,2813.73 r90 bottom
D30 "DIODE BI-DIR TRIG_R0201_D1250-5" R0201#1 3422,2830 r180 top
D31 "DIODE BI-DIR TRIG_R0201_D1250-5" R0201#1 3295,2813.73 r90 bottom
D32 "DIODE BI-DIR TRIG_ESD0402_D2315" ESD0402#1 3390,3669.37 r0 bottom
D33 "DIODE_SCHTKY_SOD-123_IC_1N5819W" SOD-123#2 3880,3689.37 r0 bottom
D34 "DIODE BI-DIR TRIG_R0201_D1250-5" R0201#1 3829,2830 r0 top
D35 "DIODE BI-DIR TRIG_R0201_D1250-5" R0201#2 3920,2855 r0 bottom
D36 "DIODE BI-DIR TRIG_R0201_D1250-5" R0201#1 3830,2855 r0 bottom
D37 "DIODE BI-DIR TRIG_R0201_D1250-5" R0201#1 3873,2830 r180 top
D38 "DIODE BI-DIR TRIG_R0201_D1250-5" R0201#1 3760,2855 r0 bottom
D39 "DIODE BI-DIR TRIG_ESD0402_D2315" ESD0402#1 3740,3669.37 r0 bottom
D40 "DIODE_SCHTKY_SOD-123_IC_1N5819W" SOD-123#1 4860,2774.37 r0 top
D41 "DIODE BI-DIR TRIG_ESD0402_D2315" ESD0402#2 4520,2939.37 r0 bottom
D42 "DIODE BI-DIR TRIG_ESD0402_D2315" ESD0402#2 4520,3094.37 r0 bottom
D43 "DIODE BI-DIR TRIG_ESD0402_D2315" ESD0402#2 4520,2899.37 r0 bottom
D44 "DIODE BI-DIR TRIG_ESD0402_D2315" ESD0402#2 4520,2854.37 r0 bottom
D45 "DIODE BI-DIR TRIG_ESD0402_D2315" ESD0402#2 4520,3054.37 r0 bottom
D46 "DIODE_SCHTKY_SOD-123_IC_1N5819W" SOD-123#1 5200,2774.37 r180 top
D47 "DIODE BI-DIR TRIG_ESD0402_D23_1" ESD0402#2 2010,270 r0 bottom
D48 "DIODE BI-DIR TRIG_ESD0402_D23_1" ESD0402#2 1930,270 r0 bottom
D49 "DIODE_SCHTKY_SOD-123_IC_1N5819W" SOD-123#2 4310,2294.37 r0 bottom
D50 "DIODE BI-DIR TRIG_R0201_D1250-5" R0201#1 3563,2830 r0 top
D51 "DIODE BI-DIR TRIG_R0201_D1250-5" R0201#1 3608,2830 r180 top
D52 "DIODE BI-DIR TRIG_R0201_D1250-5" R0201#1 3652,2830 r0 top
D53 "DIODE BI-DIR TRIG_R0201_D1250-5" R0201#1 3696,2830 r180 top
D54 "DIODE BI-DIR TRIG_R0201_D1250-5" R0201#1 3740,2830 r0 top
D55 "DIODE BI-DIR TRIG_ESD0402_D23_1" ESD0402#1 243.42,379.37 r0 bottom
D56 "DIODE BI-DIR TRIG_ESD0402_D23_1" ESD0402#1 243.42,514.37 r0 bottom
D57 "BAT54C_SOT23_BAT54C" SOT23#1 4730,1305 r270 top
D58 "DIODE_SCHTKY_SOD523_IC_RB521S-3" SOD523 5690,724.37 r0 bottom
D59 "DIODE BI-DIR TRIG_ESD0402_D23_1" ESD0402#1 4585,1305 r270 top
D60 "DIODE_SCHTKY_SOD523_IC_RB521S-3" SOD523 5375,729.37 r0 bottom
D61 "DIODE BI-DIR TRIG_ESD0402_D23_1" ESD0402#1 4045,1015 r90 top
D62 "DIODE BI-DIR TRIG_ESD0402_D23_1" ESD0402#1 4045,1125 r90 top
D63 "DIODE BI-DIR TRIG_ESD0402_D23_1" ESD0402#1 4045,775 r270 top
D64 "DIODE BI-DIR TRIG_ESD0402_D23_1" ESD0402#1 4045,905 r90 top
D65 "DIODE BI-DIR TRIG_R0201_D1250-5" R0201#1 3785,2830 r180 top
D66 "DIODE BI-DIR TRIG_R0201_D1250-5" R0201#1 3917,2830 r0 top
D67 "DIODE BI-DIR TRIG_R0201_D1250-5" R0201#1 3961,2830 r180 top
D68 "DIODE BI-DIR TRIG_R0201_D1250-5" R0201#1 4005,2830 r0 top
D69 "DIODE BI-DIR TRIG_R0201_D1250-5" R0201#1 4049,2830 r180 top
D70 "DIODE BI-DIR TRIG_R0201_D1250-5" R0201#1 4093,2830 r0 top
D71 "DIODE BI-DIR TRIG_R0201_D1250-5" R0201#1 4138,2830 r180 top
D72 "DIODE BI-DIR TRIG_R0201_D1250-5" R0201#1 4183,2830 r0 top
D73 "DIODE BI-DIR TRIG_R0201_D1250-5" R0201#1 4227,2830 r180 top
D74 "DIODE BI-DIR TRIG_ESD0402_D2315" ESD0402#1 3830,320 r0 top
D75 "DIODE BI-DIR TRIG_ESD0402_D2315" ESD0402#1 3910,320 r180 top
D76 "DIODE BI-DIR TRIG_ESD0402_D2315" ESD0402#1 4180,320 r0 top
D77 "DIODE BI-DIR TRIG_ESD0402_D2315" ESD0402#1 4260,320 r180 top
D78 "DIODE BI-DIR TRIG_ESD0402_D2315" ESD0402#1 175,3290 r180 top
D79 "DIODE BI-DIR TRIG_ESD0402_D2315" ESD0402#1 1720,3460 r90 top
D80 "DIODE BI-DIR TRIG_ESD0402_D2315" ESD0402#1 1250,3335 r90 top
D81 "DIODE BI-DIR TRIG_ESD0402_D2315" ESD0402#1 1715,3670 r270 top
D82 "DIODE BI-DIR TRIG_ESD0402_D2315" ESD0402#1 1220,3620 r0 bottom
D83 "DIODE BI-DIR TRIG_ESD0402_D2315" ESD0402#1 95,3290 r0 top
D85 "DIODE BI-DIR TRIG_ESD0402_D2315" ESD0402#1 3055,265 r0 bottom
D86 "DIODE BI-DIR TRIG_ESD0402_D2315" ESD0402#2 3135,265 r0 bottom
D87 "DIODE BI-DIR TRIG_ESD0402_D2315" ESD0402#1 3215,265 r0 bottom
D88 "DIODE BI-DIR TRIG_ESD0402_D2315" ESD0402#2 3295,265 r0 bottom
DN1 "TVS ARR COMA_SOT23_SM712" SOT23#1 4950,585 r90 top
DN2 "TVS ARR COMA_SOT23_SM712" SOT23#1 4950,415 r90 top
F1 "FUSE_F1812_SMD1812P200TF16" F1812 460,3110 r270 top
J1 "DF40C-100DP_DF40C-100DP-0P4V_DF" DF40C-100DP-0P4V 2057.97,517.79 r0 top
J2 "DF40C-100DP_DF40C-100DP-0P4V_DF" DF40C-100DP-0P4V 3064.57,517.79 r0 top
J3 "SGDBM-05-100P-H10_DF40HC-100DS-" DF40HC-100DS-0P4V 2057.98,2353.81 r0 top
J4 "SGDBM-05-100P-H10_DF40HC-100DS-" DF40HC-100DS-0P4V 3064.58,2353.81 r0 top
J5 "DC-044A-20A_DC_IN_TH_3P_10R1X11" DC_IN_TH_3P_10R1X11R6 527.57,3586.42 r270 top
J6 "HY911130A_HY911130A_HY911130A" HY911130A#1 2803.6,3425.2 r0 top
J7 "HY911130A_HY911130A_HY911130A" HY911130A#2 2091.4,3425.2 r0 top
J8 "TYPE-C-24P_USB-C-SMD_TYC-324G_T" USB-C-SMD_TYC-324G 1024.8,3651.18 r180 top
J9 "USB3D0_USB2D0-A-D_USB3D0-AF-18P" USB3D0-AF-18P 4837.44,3515.02 r180 top
J10 "USB-A-D_USB-A-D_USB-A-D" USB-A-D 5557.09,3500.99 r0 top
J11 "PJ-393_AUDIO_SMD_7P_6R0X8R8_PJ-" AUDIO_SMD_7P_6R0X8R8 1474.41,3577.76 r180 top
J12 "1X2PIN_ZH1P5MM_TH_2P_A1501WV-2P" ZH1P5MM_TH_2P 4190,1305 r0 top
J13 "M2_NGFF_E_KEY_M2_NGFF_E_KEY_M2_" M2_NGFF_E_KEY 5229.41,2410.85 r0 bottom
J14 "FPC-30P_FPC-30P-0P5_FPC_0R5_30P" FPC-30P-0P5 168.33,2709.6 r270 top
J15 "FPC-30P_FPC-30P-0P5_FPC_0R5_30P" FPC-30P-0P5 168.33,2709.37 r90 bottom
J16 "HDMI-001C_HDMI-SMD_IO_HDMI-001C" HDMI-SMD 3377.4,3393.24 r90 top
J17 "HDMI-001C_HDMI-SMD_IO_HDMI-001C" HDMI-SMD 3802.6,3393.24 r90 top
J18 "HDMI-001C_HDMI-SMD_IO_HDMI-001C" HDMI-SMD 4227.8,3393.24 r90 top
J19 "M2_NGFF_M_KEY_M2_NGFF_M_KEY_M2_" M2_NGFF_M_KEY 6340.24,3273.52 r0 top
J20 "PCIEX4_64P_PCIE_64PIN_1R00_AAA-" PCIE_64PIN_1R00 192.52,1393.11 r270 top
J21 "SIM-7-1_NANO_SIM_SIM-7-1" NANO_SIM 6492.13,630.63 r270 bottom
J22 "CON4_DB2ERC-3P81-4P_WJ15EDGRC-3" DB2ERC-3P81-4P 4543.97,100.39 r180 top
J23 "MINI-PCIE_PCIE_52P_MINI-PCIE" PCIE_52P 5224.41,2400.85 r180 top
J24 "TF_CARD_TFCARD_IO_TF_CARD" TFCARD 6446.88,615.63 r90 top
J25 "1X3PIN_HDR1X3-2R54-TM-VM_HDR1X3" HDR1X3-2R54-TM-VM 70.86,422.08 r270 top
J26 "1X2PIN_GH1P25_TH_2P_1.25T-2A" GH1P25_TH_2P 4435,1305 r180 top
J27 "CON6_DB2ERC-3P81-6P_CON6" DB2ERC-3P81-6P 5343.74,100.39 r180 top
J28 "1X4PIN_PH-1X4-2P0_PH-4A" PH-1X4-2P0 4435,610 r90 top
J29 "1X4PIN_PH-1X4-2P0_PH-4A" PH-1X4-2P0 4190,611.53 r270 top
J30 "2X3PIN_HDR2X3-2R54-TM-VM_HDR2X3" HDR2X3-2R54-TM-VM 4435,1015 r270 top
J31 "2X3PIN_HDR2X3-2R54-TM-VM_HDR2X3" HDR2X3-2R54-TM-VM 4190,1015 r270 top
J32 "FPC-24P_FPC_24P_0P5_FPC_0P5_24P" FPC_24P_0P5 6639.45,2700.71 r270 top
J33 "FPC-24P_FPC_24P_0P5_FPC_0P5_24P" FPC_24P_0P5 6639.45,2700.71 r90 bottom
J34 "FPC-24P_FPC_24P_0P5_FPC_0P5_24P" FPC_24P_0P5 6639.45,2015.98 r270 top
J35 "FPC-24P_FPC_24P_0P5_FPC_0P5_24P" FPC_24P_0P5 6639.45,2015.98 r90 bottom
J36 "FPC-24P_FPC_24P_0P5_FPC_0P5_24P" FPC_24P_0P5 6639.45,1331.26 r270 top
J37 "FPC-24P_FPC_24P_0P5_FPC_0P5_24P" FPC_24P_0P5 6639.45,1331.26 r90 bottom
J38 "1X4PIN_XH2P54-4P_XH-4A" XH2P54-4P 2559.72,139.06 r0 top
J39 "SATA_SSATA_V_SATA" SSATA_V 3170.98,145.67 r180 top
J40 "CON2_DB2ERC-3P81-2P_CON2" DB2ERC-3P81-2P 3695.63,102.36 r180 top
J41 "1X5PIN_PH-1X5-2P0_PH-5A" PH-1X5-2P0 2027.2,122.05 r180 top
J42 "1X2PIN_PH-1X2-2P0_L_PH-2A" PH-1X2-2P0_L 1030,3113.87 r180 top
J43 "1X2PIN_PH-1X2-2P0_L_PH-2A" PH-1X2-2P0_L 1474.41,3113.87 r180 top
J44 "1X6PIN_PH-1X6-2P0_PH-6A" PH-1X6-2P0 1475.39,122.04 r180 top
J45 "CON2_DB2ERC-3P81-2P_CON2" DB2ERC-3P81-2P 4045,102.36 r180 top
L1 "BEAD_L0603_DISCRETE_100R 100MHZ" L0603#1 585,3664.37 r270 bottom
L2 "IND_L4520_DISCRETE_3.3UH" L4520 930,1984.37 r270 top
L3 "IND_L0518_DISCRETE_1.5UH" L0518 952,825 r270 top
L4 "IND_L2520_DISCRETE_2.2UH" L2520 2919,2575 r0 top
L7 "IND_L2520_DISCRETE_2.2UH" L2520 2194.59,2575 r0 top
L11 "BEAD_L0603_DISCRETE_100R 100MHZ" L0603#2 4475,3679.37 r0 bottom
L12 "BEAD_L0603_DISCRETE_100R 100MHZ" L0603#1 1320,3719.37 r0 bottom
L13 "BEAD_L0603_DISCRETE_100R 100MHZ" L0603#1 5300,3669.37 r90 bottom
L14 "BEAD_L0603_DISCRETE_100R 100MHZ" L0603#2 730,2490 r0 bottom
L15 "BEAD_L0603_DISCRETE_100R 100MHZ" L0603#1 855,2490 r0 bottom
L16 "IND_L4520_DISCRETE_3.3UH" L4520 6005,2705 r90 top
L17 "IND_L4520_DISCRETE_3.3UH" L4520 930,1509.37 r270 top
L18 "IND_L4520_DISCRETE_3.3UH" L4520 6010,2095 r90 top
L19 "BEAD_L0603_DISCRETE_1K 100MHZ" L0603#1 1110,2895 r90 top
L20 "IND_L4520_DISCRETE_3.3UH" L4520 540,2420 r270 top
L21 "IND_L4520_DISCRETE_3.3UH" L4520 925,1749.37 r0 top
L22 "BEAD_L0603_DISCRETE_100R 100MHZ" L0603#1 5690,824.37 r0 bottom
L23 "BEAD_L0603_DISCRETE_100R 100MHZ" L0603#1 5380,824.37 r0 bottom
L24 "BEAD_L0603_DISCRETE_100R 100MHZ" L0603#2 5041.57,599.37 r0 bottom
L25 "IND_L4520_DISCRETE_3.3UH" L4520 6220,2095 r0 top
L26 "IND_L4520_DISCRETE_3.3UH" L4520 935,1129.37 r270 top
L27 "BEAD_L0603_DISCRETE_1K 100MHZ" L0603#1 960,2895 r90 top
L28 "BEAD_L0603_DISCRETE_1K 100MHZ" L0603#1 1555,2895 r90 top
L29 "BEAD_L0603_DISCRETE_1K 100MHZ" L0603#1 1405,2895 r90 top
LED1 "LED_LED_HS_0602_UR_HS-0602-UR" LED_HS_0602_UR 5963.34,3732.29 r0 top
LED2 "LED_LED_HS_0602_UR_HS-0602-UG" LED_HS_0602_UR 6143.1,3732.29 r0 top
MARK "ID" MARK#1 1118.11,-98.42 r0 top
MARK "ID" MARK#2 5992.91,-98.42 r0 top
MARK "ID" MARK#3 5992.91,3877.95 r180 top
MARK "ID" MARK#4 818.11,3877.95 r180 top
MARK "ID" MARK#5 1118.11,-98.42 r0 bottom
MARK "ID" MARK#6 818.11,3877.95 r0 bottom
MARK "ID" MARK#7 5992.91,3877.95 r0 bottom
MARK "ID" MARK#8 5992.91,-98.42 r0 bottom
MARK "ID" MARK#9 1209,848 r0 top
MARK "ID" MARK#10 394,3548 r0 top
MARK "ID" MARK#11 5994,127 r0 top
MARK "ID" MARK#12 6267,2381 r0 top
MARK "ID" MARK#13 619,534 r0 bottom
MARK "ID" MARK#14 1101,3359 r0 bottom
MARK "ID" MARK#15 6142,3507 r0 bottom
MARK "ID" MARK#16 5847,343 r0 bottom
P1 "MIC_POM_MIC2-4R00-TM_IC_MIC_POM" MIC2-4R00-TM 135,3409.37 r0 top
Q1 "MOSFET_P_SOT23_IC_SSM3J328R-LF" SOT23#2 3935,1215 r0 bottom
Q2 "NPN_SOT23_IC_SS8050" SOT23#2 3935,855 r0 bottom
Q3 "MOSFET N_SOT23_WNM2016-3/TR" SOT23#1 1580,3434.37 r90 bottom
Q4 "MOSFET N_SOT23_WNM2016-3/TR" SOT23#1 1315,3434.37 r270 bottom
Q5 "MOSFET_P_SOT23_IC_SSM3J328R-LF" SOT23#1 505,539.37 r270 top
Q6 "2SK3018_SOT23_IC_2SK3018" SOT23#1 3330,2640 r0 top
Q7 "2SK3018_SOT23_IC_2SK3018" SOT23#1 3490,2565 r270 bottom
Q8 "2SK3018_SOT23_IC_2SK3018" SOT23#1 3635,2440 r270 bottom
